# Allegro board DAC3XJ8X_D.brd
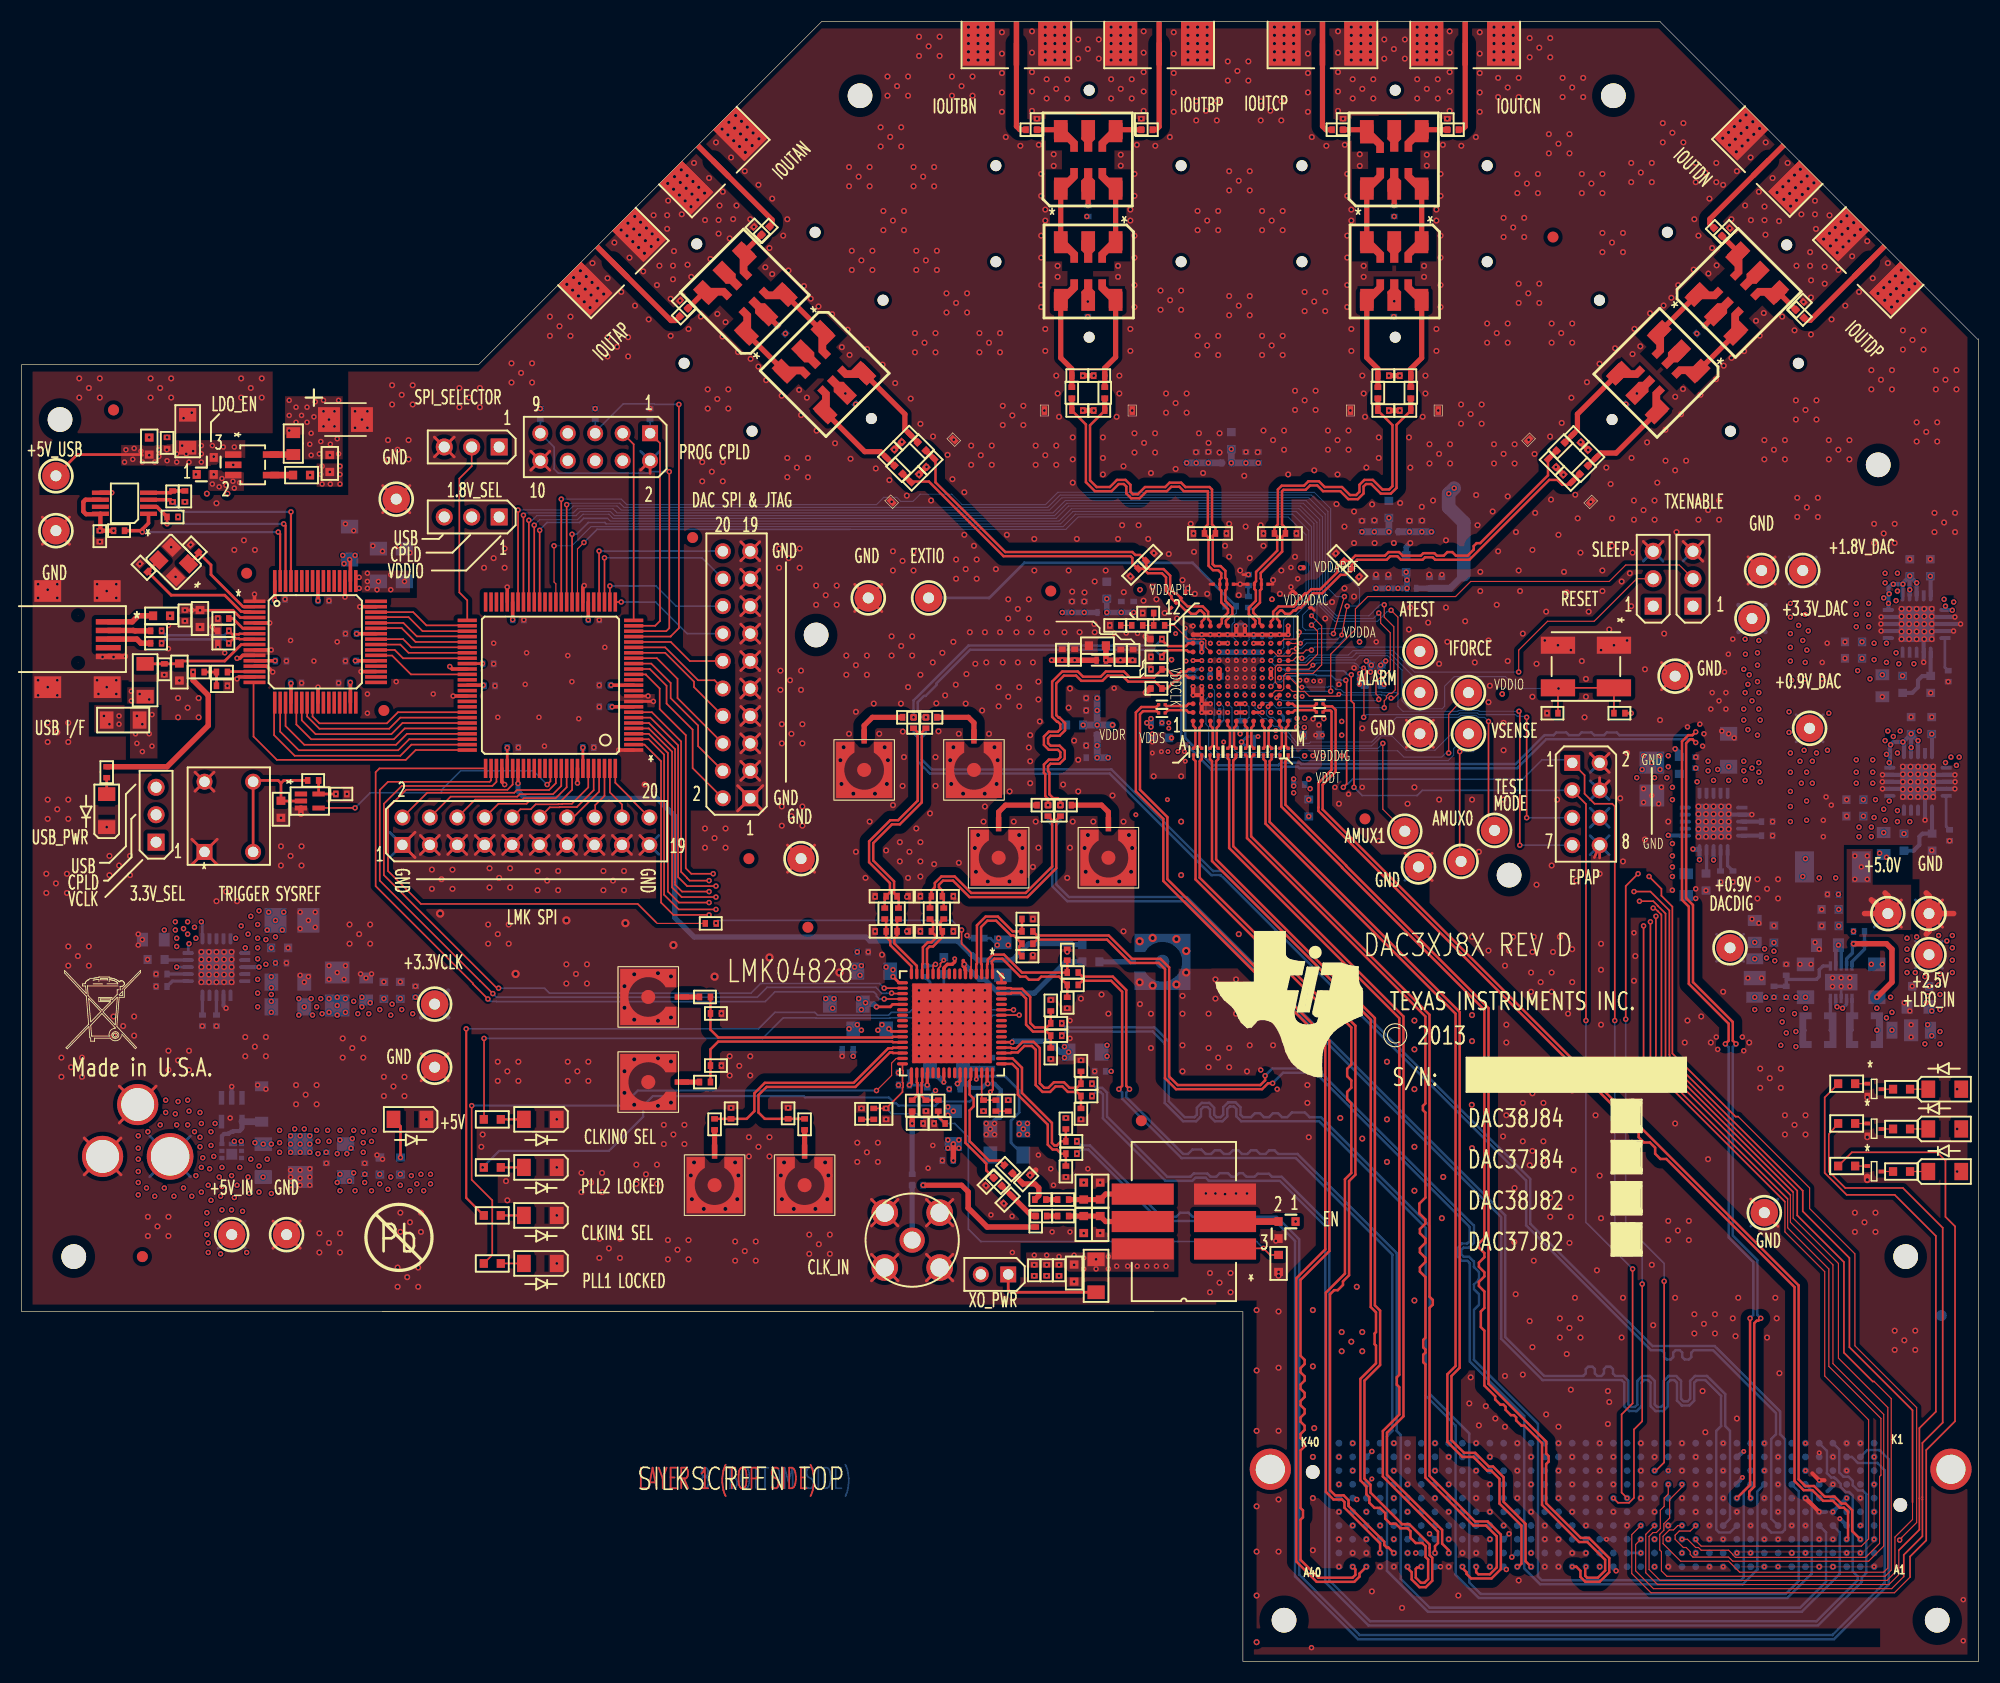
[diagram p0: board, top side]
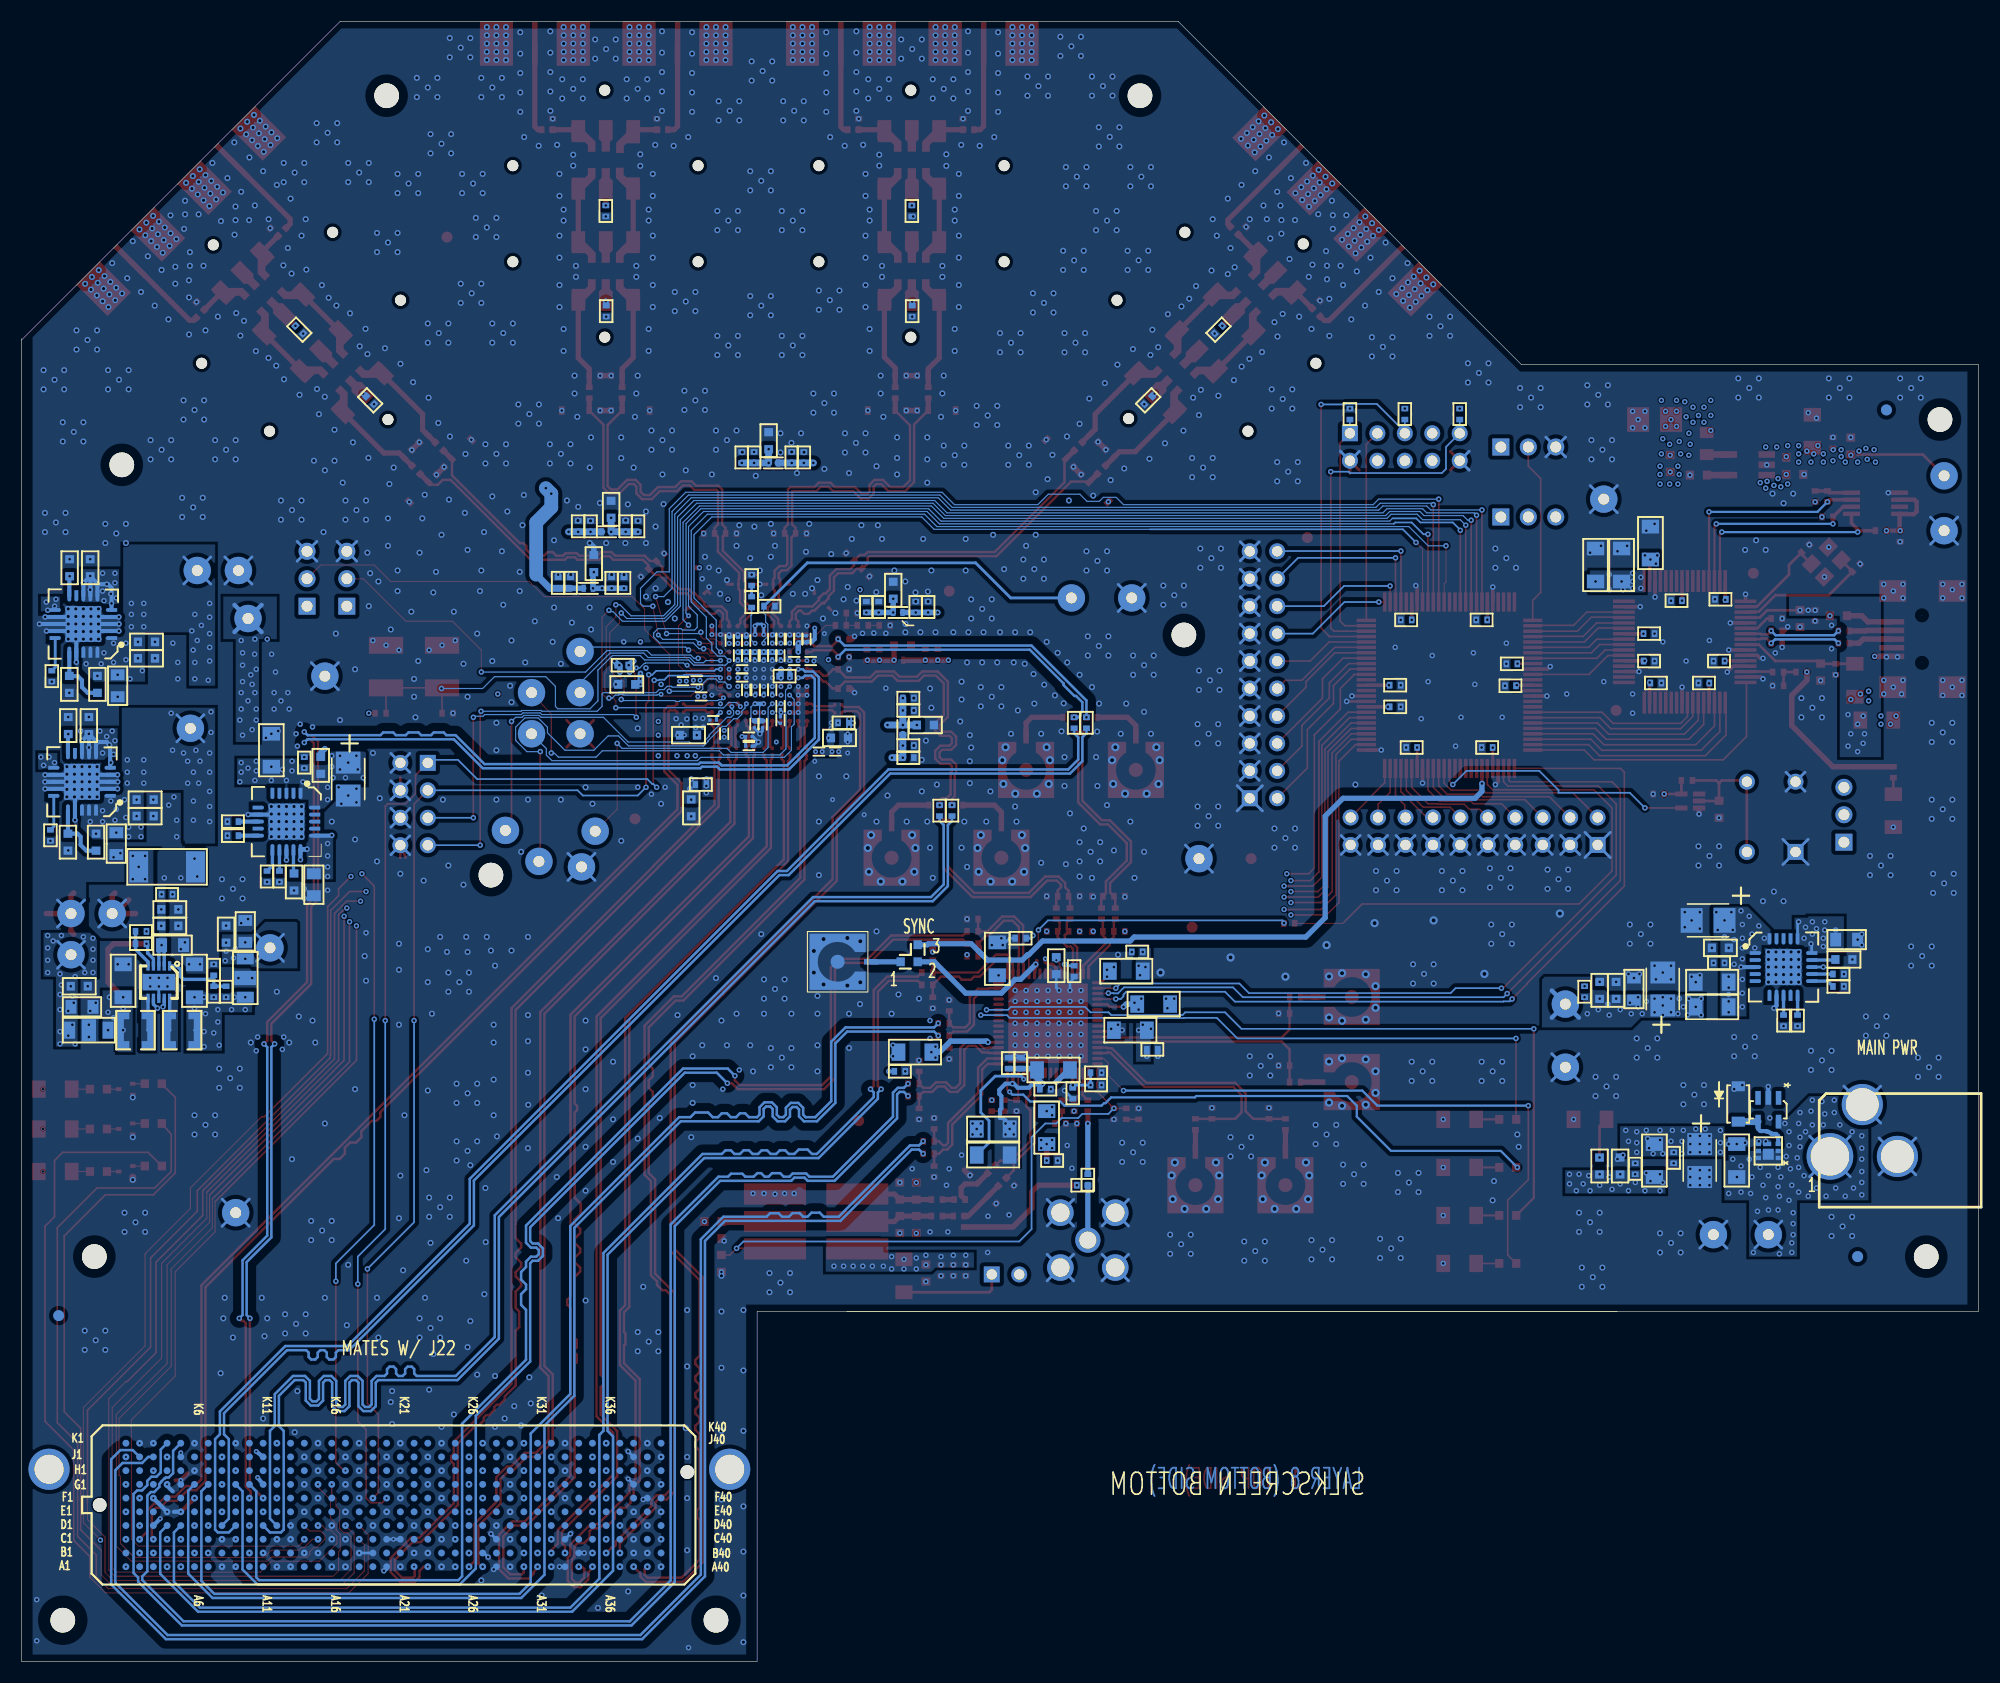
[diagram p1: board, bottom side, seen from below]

Outline 181.1 x 151.76 mm; copper layers: TOP, L2_GND, L3_PWR, L4_GND, L5_GND, L6_PWR, L7_GND, BOTTOM. Coordinates in mm from the lower left corner of the outline.
Outline path: 33.4,32.39 113.03,32.39 113.03,0 181.1,0 181.1,122.43 ; 104.77,32.39 0,32.39 0,120.02 42.29,120.02 74.04,151.76 151.64,151.76 181.1,122.3

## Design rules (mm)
constraint set DEFAULT: min track width 0.102
net group AOUT: nets ANOUT APOUT
net group B_OUT: nets BN_OUT BP_OUT
net group BOUT: nets BNOUT BPOUT
net group C_OUT: nets CN_OUT CP_OUT
net group CAR_SYSREF: nets CAR_SYSREFM CAR_SYSREFP
net group CLK: nets CLKN CLKP
net group CLK_LAO: nets CLK_LAO_0M CLK_LAO_0P
net group CLKIN1: nets CLKIN1N CLKIN1P
net group CLKLA: nets CLKLA_0N CLKLA_0P
net group COUT: nets CNOUT CPOUT
net group D_OUT: nets DN_OUT DP_OUT
net group DCLK_: nets DCLK_N DCLK_P
net group DCLKOUT0: nets DCLKOUT0N DCLKOUT0P
net group DCLKOUT2: nets DCLKOUT2N DCLKOUT2P
net group DCLKOUT8: nets DCLKOUT8N DCLKOUT8P
net group DIFFPAIR0: nets DP0_C2M_N_A DP0_C2M_P_A
net group DIFFPAIR1: nets DP7_C2M_N_A DP7_C2M_P_A
net group DIFFPAIR2: nets DP1_C2M_N_A DP1_C2M_P_A
net group DIFFPAIR3: nets DP2_C2M_N_A DP2_C2M_P_A
net group DIFFPAIR4: nets DP3_C2M_N_A DP3_C2M_P_A
net group DIFFPAIR5: nets DP4_C2M_N_A DP4_C2M_P_A
net group DIFFPAIR6: nets DP5_C2M_N_A DP5_C2M_P_A
net group DIFFPAIR7: nets DP6_C2M_N_A DP6_C2M_P_A
net group DIFFPAIR8: nets AN_OUT AP_OUT
net group DIFFPAIR9: nets GTXCLKM GTXCLKP
net group DIFFPAIR10: nets FMC_SYSREF_N FMC_SYSREF_P
net group DIFFPAIR11: nets FMC_DACCLK_N FMC_DACCLK_P
net group DOUT: nets DNOUT DPOUT
net group FPGA_CLK1: nets FPGA_CLK1N FPGA_CLK1P
net group FPGA_CLK2: nets FPGA_CLK2N FPGA_CLK2P
net group GTX_CLK: nets GTX_CLKM GTX_CLKP
net group IOUTA: nets IOUTAN IOUTAP
net group IOUTB: nets IOUTBN IOUTBP
net group IOUTC: nets IOUTCN IOUTCP
net group IOUTD: nets IOUTDN IOUTDP
net group OSCIN: nets OSCIN_N OSCIN_P
net group OUT_A: nets OUT_AN OUT_AP
net group OUT_B: nets OUT_BN OUT_BP
net group OUT_C: nets OUT_CN OUT_CP
net group OUT_D: nets OUT_DN OUT_DP
net group RX0: nets RX0N RX0P
net group RX1: nets RX1N RX1P
net group RX2: nets RX2N RX2P
net group RX3: nets RX3N RX3P
net group RX4: nets RX4N RX4P
net group RX5: nets RX5N RX5P
net group RX6: nets RX6N RX6P
net group RX7: nets RX7N RX7P
net group SDCLKOUT1: nets SDCLKOUT1N SDCLKOUT1P
net group SDCLKOUT3: nets SDCLKOUT3N SDCLKOUT3P
net group SDCLKOUT9: nets SDCLKOUT9N SDCLKOUT9P
net group SYNC: nets SYNCN SYNCP
net group SYS_: nets SYS_N SYS_P
net group SYSRE: nets SYSREF_M SYSREF_P
net group SYSREF: nets SYSREFN SYSREFP
net group USB_M: nets USB_DM USB_DP

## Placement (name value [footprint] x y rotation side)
C1  0.01uF  [0402]  94.49 79.25 0 top
C3  10uF  [0603]  119.13 78.99 270 bottom
C4  .1uF  [0201]  112.52 86.74 270 bottom
C5  .1uF  [0201]  113.28 86.74 270 bottom
C6  10uF  [0603]  99.57 94.01 180 top
C7  .1uF  [0201]  109.6 92.58 0 bottom
C8  0.01uF  [0402]  96.65 79.25 180 top
C9  .1uF  [0201]  108.08 92.58 180 bottom
C10  10uF  [0603]  128.14 101.6 90 bottom
C11  10uF  [0603]  119.38 85.72 0 bottom
C12  0.01uF  [0402]  82.04 87.38 0 top
C13  .1uF  [0201]  117.09 87.12 180 bottom
C14  .1uF  [0201]  111.63 89.92 90 bottom
C15  10uF  [0603]  125.09 90.42 0 bottom
C16  0.01uF  [0402]  84.2 87.38 180 top
C17  10uF  [0603]  100.43 99.14 90 bottom
C18  10uF  [0603]  105.41 85.47 180 bottom
C20  10uF  [0603]  111.96 112.98 90 bottom
C21  10uF  [0603]  97.46 86.66 180 bottom
C22  10uF  [0603]  126.54 106.63 90 bottom
C23  .1uF  [0201]  119.89 90.73 0 bottom
C24  .1uF  [0201]  118.62 90.81 0 bottom
C25  .1uF  [0201]  109.22 94.62 90 bottom
C26  .1uF  [0201]  108.46 94.62 90 bottom
C27  .1uF  [0201]  105.79 84.2 180 bottom
C28  .1uF  [0201]  107.31 84.2 0 bottom
C31  .1uF  [0201]  109.98 94.62 90 bottom
C32  .1uF  [0201]  115.57 94.49 90 bottom
C33  .1uF  [0201]  113.79 85.6 180 bottom
C34  .1uF  [0201]  113.79 84.71 180 bottom
C35  .1uF  [0201]  112.39 84.2 90 top
C36  .1uF  [0201]  111.63 84.2 90 top
C37  .1uF  [0201]  109.22 84.2 90 top
C38  .1uF  [0201]  108.46 84.2 90 top
C39  .1uF  [0201]  105.54 88.54 0 top
C40  .1uF  [0201]  105.54 87.78 0 top
C41  .01uF  [0603]  11.81 112.48 90 top
C42  27pF  [0402]  16 103 135 top
C43  100uF  [1206]  35.43 101.47 90 bottom
C44  4.7uF  [0603]  16.51 96.52 270 top
C45  .1uF  [0402]  15.11 96.8 270 top
C46  4.7uF  [0603]  14.61 91.57 270 top
C47  .01uF  [0603]  25.91 109.79 0 top
C48  .1uF  [0402]  13.21 91.82 270 top
C49  100uF  [1206]  30.35 103.51 90 bottom
C50  .1uF  [0402]  101.22 95.89 180 top
C51  22pF  [0402]  18.67 95.38 180 top
C52  22pF  [0402]  18.67 94.23 180 top
C53  .001uF  [0402]  104.27 97.03 180 top
C54  10uF  [1206]  15.37 113.85 90 top
C55  27pF  [0402]  11.3 101.22 135 top
C56  10uF  [1206]  33.02 101.47 90 bottom
C57  1uF  [0402]  83.82 52.58 270 bottom
C58  .1uF  [0402]  81.66 54.48 180 bottom
C59  0.01uF  [0402]  81.66 53.34 180 bottom
C60  .1uF  [0402]  80.01 50.67 270 top
C61  .68uF  [0402]  78.87 50.67 270 top
C62  3900pF  [0402]  90.17 51.44 270 top
C63  47pF  [0402]  89.03 51.44 270 top
C64  .1uF  [0402]  86.36 52.96 180 bottom
C65  0.01uF  [0402]  88.65 55.37 90 bottom
C66  1uF  [0402]  89.79 55.37 90 bottom
C67  .1uF  [0402]  97.28 62.61 0 top
C68  .1uF  [0402]  97.28 63.75 0 top
C69  0.01uF  [0402]  88.65 66.93 180 bottom
C70  0.01uF  [0402]  77.85 65.66 0 bottom
C71  0.01uF  [0402]  99.82 54.61 180 bottom
C72  0.01uF  [0402]  76.45 56.64 180 bottom
C73  0.01uF  [0402]  85.72 46.36 180 bottom
C74  .1uF  [0402]  98.55 53.47 0 top
C75  .1uF  [0402]  98.55 52.32 0 top
C78  .1uF  [0402]  83.69 51.44 90 top
C79  .1uF  [0402]  63.25 61.49 180 top
C80  .1uF  [0402]  94.28 42.74 180 top
C81  100pF  [0603]  97.41 35.94 90 top
C82  .1uF  [0402]  91.31 45.56 135 top
C83  .1uF  [0402]  63.25 53.62 180 top
C84  2200pF  [0402]  96.01 36.2 90 top
C85  10pF  [0402]  94.87 36.2 90 top
C86  .1uF  [0402]  95.76 57.91 180 top
C87  10uF  [0603]  85.34 64.39 270 bottom
C88  .1uF  [0402]  83.69 63.88 270 bottom
C89  .1uF  [0402]  95.76 59.06 180 top
C90  .1uF  [0402]  93.73 36.2 90 top
C91  .1uF  [0402]  64.13 49.71 270 top
C92  .1uF  [0402]  90.32 44.39 135 top
C93  .1uF  [0402]  72.47 49.71 270 top
C94  .1uF  [0402]  97.15 46.99 0 top
C95  .1uF  [0402]  97.15 48.13 0 top
C96  10uF  [0805]  12.19 66.8 180 bottom
C97  .1uF  [0402]  24 64.64 0 bottom
C98  1.0uF  [0603]  23.88 66.04 0 bottom
C99  47uF  [1206]  24.64 62.87 0 bottom
C100  4.7uF  [TANT_B]  25.02 68.58 0 bottom
C101  33uF  [TANT_B]  29.21 62.23 90 bottom
C102  10uF  [0805]  31.88 62.23 90 bottom
C103  .1uF  [0402]  36.45 61.98 90 bottom
C104  .01uF  [0603]  33.53 62.1 90 bottom
C105  .01uF  [0603]  35.05 62.1 90 bottom
C106  1.0uF  [0603]  12.45 64.96 180 bottom
C107  10uF  [0805]  154.05 71.88 270 bottom
C108  .1uF  [0402]  154.94 83.19 90 bottom
C109  1.0uF  [0603]  153.42 82.93 90 bottom
C110  47uF  [1206]  157.99 84.33 90 bottom
C113  4.7uF  [TANT_B]  150.88 81.66 270 bottom
C116  1.0uF  [0603]  155.89 72.14 270 bottom
C117  .01uF  [0603]  167.39 69.6 180 bottom
C119  .01uF  [0603]  175.77 62.48 180 bottom
C120  100pF  [0603]  116.33 36.83 90 top
C121  .1uF  [0402]  89.61 44.39 45 top
C122  .1uF  [0402]  82.42 51.44 90 top
C123  .01uF  [0603]  33.16 45.85 90 bottom
C124  .1uF  [0402]  28.21 46.61 270 bottom
C125  1uF  [0402]  31.76 45.59 90 bottom
C126  2.2uF  [0603]  174.75 101.22 90 bottom
C127  1.0uF  [0603]  176.66 101.22 90 bottom
C128  1.0uF  [0603]  169.54 94.36 180 bottom
C129  .01uF  [0603]  169.54 92.84 180 bottom
C130  10uF  [0805]  172.21 90.3 270 bottom
C133  .015uF  [0402]  178.31 91.19 270 bottom
C134  1.0uF  [0603]  176.78 86.61 90 bottom
C135  2.2uF  [0603]  174.88 86.61 90 bottom
C136  .015uF  [0402]  178.44 76.45 270 bottom
C137  1.0uF  [0603]  169.67 79.76 180 bottom
C138  .01uF  [0603]  169.67 78.23 180 bottom
C139  10uF  [0805]  172.34 75.69 270 bottom
C143  10uF  [0805]  167.13 66.29 180 bottom
C144  10uF  [0805]  175.51 60.58 180 bottom
C145  22uF  [1206]  165.1 62.99 90 bottom
C146  10uF  [0805]  160.4 67.56 90 bottom
C147  22uF  [1206]  171.7 62.99 90 bottom
C148  33pF  [0402]  162.18 61.98 90 bottom
C149  .01uF  [0603]  162.18 67.31 90 bottom
C150  1.0uF  [0603]  167.39 68.07 180 bottom
C151  4.7uF  [TANT_B]  29.97 114.94 0 top
C152  .1uF  [0402]  52.45 84.58 180 bottom
C153  .1uF  [0402]  45.47 84.58 180 bottom
C154  .1uF  [0402]  43.18 92.33 180 bottom
C155  .1uF  [0402]  43.31 90.3 180 bottom
C156  .1uF  [0402]  53.98 88.35 0 bottom
C157  .1uF  [0402]  29.84 90.55 0 bottom
C158  .1uF  [0402]  27.94 98.17 180 bottom
C159  .1uF  [0402]  30.48 95.12 0 bottom
C160  .1uF  [0402]  25.4 90.55 180 bottom
C161  .1uF  [0402]  24 92.58 180 bottom
C162  .1uF  [0402]  53.98 90.35 0 bottom
C163  .1uF  [0402]  23.88 98.3 180 bottom
C164  .1uF  [0402]  30.48 92.58 0 bottom
C165  .1uF  [0402]  52.96 96.39 180 bottom
C166  .1uF  [0402]  45.97 96.39 180 bottom
C167  .1uF  [0402]  111.89 97.66 180 bottom
C168  .001uF  [0402]  141.68 87.76 180 top
C169  .1uF  [0201]  111.63 94.62 90 bottom
C170  .1uF  [0201]  114.81 94.49 90 bottom
C171  .1uF  [0201]  114.43 91.06 180 bottom
C172  .01uF  [0201]  110.87 94.62 90 bottom
C173  .01uF  [0201]  114.05 94.49 90 bottom
C174  .1uF  [0201]  114.43 91.82 180 bottom
C175  .1uF  [0201]  110.87 87.12 90 bottom
C176  .1uF  [0201]  116.08 85.85 270 bottom
C177  .1uF  [0201]  112.39 89.92 90 bottom
C178  .1uF  [0201]  113.16 89.92 90 bottom
C179  .1uF  [0201]  114.05 89.92 90 bottom
C180  .1uF  [0201]  110.87 88.39 270 bottom
C181  .1uF  [0201]  118.21 89.31 0 bottom
C182  .1uF  [0201]  110.87 93.09 270 bottom
C183  .1uF  [0201]  111.63 93.09 270 bottom
C184  .1uF  [0201]  112.39 93.09 270 bottom
C185  .1uF  [0201]  113.28 93.09 270 bottom
C186  .1uF  [0201]  114.05 93.09 270 bottom
C187  .1uF  [0201]  114.81 93.09 270 bottom
C188  .1uF  [0201]  109.98 84.2 90 top
C189  .1uF  [0201]  110.74 84.2 90 top
C190  .1uF  [0201]  120.14 87.86 180 top
C191  .1uF  [0201]  120.14 88.62 180 top
C192  .1uF  [0201]  116.46 84.2 90 top
C193  .1uF  [0201]  117.22 84.2 90 top
C194  .1uF  [0201]  115.7 84.2 90 top
C195  .1uF  [0201]  114.93 84.2 90 top
C196  .1uF  [0201]  113.28 84.2 90 top
C197  .1uF  [0201]  114.05 84.2 90 top
C198  .1uF  [0402]  84.84 51.44 90 top
C199  .01uF  [0603]  24 78.87 270 top
C200  .1uF  [0402]  29.59 80.28 0 top
C206  .1uF  [0402]  94.36 41.22 180 top
C207  .1uF  [0402]  167.64 70.99 0 bottom
C235  47uF  [TANT_B]  25.79 46.36 270 bottom
C236  .1uF  [0402]  7.24 104.14 90 top
C340  1uF  [0402]  81.15 69.22 90 top
C341  1uF  [0402]  79.88 69.22 90 top
C343  0.01uF  [0402]  126.49 99.82 90 bottom
C344  1uF  [0402]  125.35 99.82 90 bottom
C345  0.01uF  [0402]  131.44 99.82 90 bottom
C346  1uF  [0402]  130.3 99.82 90 bottom
C347  0.01uF  [0402]  96.32 93.17 90 top
C348  1uF  [0402]  97.46 93.17 90 top
C349  0.01uF  [0402]  102.87 93.14 90 top
C350  1uF  [0402]  101.73 93.14 90 top
C351  0.01uF  [0402]  102.92 97.59 90 bottom
C352  1uF  [0402]  101.78 97.59 90 bottom
C353  0.01uF  [0402]  98.35 97.59 90 bottom
C354  1uF  [0402]  97.21 97.59 90 bottom
C355  0.01uF  [0402]  124.05 105.05 90 bottom
C356  1uF  [0402]  125.2 105.05 90 bottom
C357  0.01uF  [0402]  128.45 105.05 90 bottom
C358  1uF  [0402]  129.59 105.05 90 bottom
C359  0.01uF  [0402]  113.31 111.43 90 bottom
C360  1uF  [0402]  114.45 111.43 90 bottom
C361  0.01uF  [0402]  109.83 111.43 90 bottom
C362  1uF  [0402]  108.71 111.43 90 bottom
C363  0.01uF  [0402]  99.03 89.15 180 bottom
C364  1uF  [0402]  99.03 88.01 180 bottom
C365  0.01uF  [0402]  99.03 84.76 180 bottom
C366  1uF  [0402]  99.03 83.64 180 bottom
D1  LED BLUE  [LED_1206]  35.94 50.17 0 top
D2  LED BLUE  [LED_1206]  177.99 52.96 180 top
D3  LED BLUE  [LED_1206]  177.99 49.28 180 top
D4  LED GREEN  [LED_1206]  48.01 50.17 0 top
D5  LED GREEN  [LED_1206]  48.01 41.28 0 top
D6  LED GREEN  [LED_1206]  48.01 36.83 0 top
D7  LED GREEN  [LED_1206]  48.01 45.72 0 top
D8  LED AMBER  [LED_1206]  7.87 78.74 270 top
D9  MMSZ5235B  [DIODE_SM_SOD_123]  22.23 51.59 270 bottom
D11  LED BLUE  [LED_1206]  177.99 45.34 180 top
F1  FUSE 2.0A 63V FAST  [1206]  22.36 46.36 90 bottom
FB2  120 OHM @ 100MHz  [1206]  86.23 49.4 90 bottom
FB3  120 OHM @ 100MHz  [1206]  91.19 49.28 180 bottom
FB4  120 OHM @ 100MHz  [1206]  91.19 46.86 0 bottom
FB5  120 OHM @ 100MHz  [1206]  85.6 54.74 180 bottom
FB6  120 OHM @ 100MHz  [1206]  78.87 63.88 0 bottom
FB7  120 OHM @ 100MHz  [1206]  78.49 58.42 0 bottom
FB8  120 OHM @ 100MHz  [1206]  76.33 60.83 0 bottom
FB9  120 OHM @ 100MHz  [1206]  98.42 56.39 180 bottom
FB10  120 OHM @ 100MHz  [1206]  90.8 65.02 270 bottom
FB15  50 OHM @ 100MHz  [1206]  11.43 90.81 90 top
FB16  50 OHM @ 100MHz  [1206]  9.4 87.12 0 top
FB17  120 OHM @ 100MHz  [1206]  99.44 35.69 270 top
FB18  120 OHM @ 100MHz  [IND_0402]  99.92 92.66 0 top
FB19  120 OHM @ 100MHz  [IND_0402]  128.65 99.31 180 bottom
FB20  50 OHM @ 100MHz  [1206]  29.98 46.36 90 bottom
FB24  50 OHM @ 100MHz  [1206]  24.64 60.58 180 bottom
FB25  120 OHM @ 100MHz  [IND_0402]  100 97.08 0 bottom
FB29  120 OHM @ 100MHz  [IND_0402]  99.54 86.23 90 bottom
FB30  27uF  [1206_BEAD_NFM31P]  160.4 63.25 90 bottom
FB31  27uF  [1206_BEAD_NFM31P]  174.88 58.42 0 bottom
FB32  120 OHM @ 100MHz  [IND_0402]  111.53 110.92 0 bottom
FB33  120 OHM @ 100MHz  [IND_0402]  126.97 104.55 180 bottom
FB34  1K  [1810]  167.64 73.53 180 bottom
FB36  1K @ 100MHz  [0603]  28.52 110.87 90 top
GP1  GND PAD  [TESTPAD20_30]  80.52 107.33 315 top
GP2  GND PAD  [TESTPAD20_30]  86.27 113.08 135 top
GP3  GND PAD  [TESTPAD20_30]  94.66 115.77 270 top
GP4  GND PAD  [TESTPAD20_30]  102.78 115.77 90 top
GP5  GND PAD  [TESTPAD20_30]  122.98 115.77 270 top
GP6  GND PAD  [TESTPAD20_30]  131.11 115.77 90 top
GP7  GND PAD  [TESTPAD20_30]  145.22 107.32 45 top
GP8  GND PAD  [TESTPAD20_30]  139.47 113.06 225 top
J1  SMP_PCB_SMT  [SMP_B120]  77.98 82.51 180 top
J2  SMA END LAUNCH  [SMA_SMEL_DUAL_PSF-S01_250X215]  53.24 130.95 45 top
J3  SMP_PCB_SMT  [SMP_B120]  88.14 82.51 180 top
J4  SMA END LAUNCH  [SMA_SMEL_DUAL_PSF-S01_250X215]  62.58 140.29 45 top
J5  SMP_PCB_SMT  [SMP_B120]  90.42 74.38 180 top
J6  SMA END LAUNCH  [SMA_SMEL_DUAL_PSF-S01_250X215]  105.28 151.76 0 top
J7  SMP_PCB_SMT  [SMP_B120]  100.58 74.38 180 top
J8  SMA END LAUNCH  [SMA_SMEL_DUAL_PSF-S01_250X215]  92.07 151.76 0 top
J9  SMA END LAUNCH  [SMA_SMEL_DUAL_PSF-S01_250X215]  120.4 151.76 0 top
J10  SMA END LAUNCH  [SMA_SMEL_DUAL_PSF-S01_250X215]  133.6 151.76 0 top
J11  SMA END LAUNCH  [SMA_SMEL_DUAL_PSF-S01_250X215]  163.1 140.34 315 top
J12  SMA END LAUNCH  [SMA_SMEL_DUAL_PSF-S01_250X215]  172.44 131 315 top
J13  SMP_PCB_SMT  [SMP_B120]  58 61.49 90 top
J14  USB_MINI_AB  [CON_SMRT_USBMNE20_F]  4.57 94.62 0 top
J15  HTSW-105-07-G-D  [HDR_THVT_2X5_100_M]  58.17 113.67 270 top
J16  CON_SMVT_40x10_SEAM  [CON_SMVT_40X10_ASP-134487-01]  146.69 14.48 0 bottom
J17  SMB_THVT_REC  [SMA_THVT_312X312]  82.42 38.99 180 top
J18  SMP_PCB_SMT  [SMP_B120]  58 53.62 90 top
J19  SMP_PCB_SMT  [SMP_B120]  64.13 44.08 180 top
J20  SMP_PCB_SMT  [SMP_B120]  72.47 44.08 180 top
J21  HMTSW-104-07-G-D-.240  [HDR_THVT_2X4_100_M]  143.51 83.16 0 top
J22  SMP_PCB_SMT  [SMP_B120]  105.58 64.75 90 bottom
J23  CONN JACK PWR  [CON_RAPC722_JACK_THVT_3]  10.62 46.74 90 bottom
J24  HMTSW-110-07-G-D-.240  [HDR_THVT_2X10_100_M]  67.44 79.88 180 top
J25  HMTSW-110-07-G-D-.240  [HDR_THVT_2X10_100_M]  35.24 75.56 90 top
JP1  Jumper_1x3_100_430L  [HDR_THVT_1X3_100_M]  154.69 97.66 180 top
JP2  HDR, THVT, 2POS  [HDR_THVT_1X2_100_M]  91.31 35.81 270 top
JP3  Jumper_1x3_100_430L  [HDR_THVT_1X3_100_M]  44.2 112.4 270 top
JP4  Jumper_1x3_100_430L  [HDR_THVT_1X3_100_M]  151 97.66 180 top
JP5  Jumper_1x3_100_430L  [HDR_THVT_1X3_100_M]  44.2 105.92 270 top
JP6  Jumper_1x3_100_430L  [HDR_THVT_1X3_100_M]  12.45 75.82 180 top
L17  2.2uH  [LPS3015]  170.56 58.42 0 bottom
L18  2.2uH  [LPS3015]  166.24 58.42 180 bottom
MT1  STANDOFF,  HEX, 4-40 X 1 1/4", ALUM  [MFG125_PLATED]  171.83 110.74 0 top
MT2  STANDOFF,  HEX, 4-40 X 1 1/4", ALUM  [MFG125_PLATED]  4.83 37.47 270 top
MT3  STANDOFF,  HEX, 4-40 X 1 1/4", ALUM  [MFG125_PLATED]  147.32 144.91 0 top
MT4  STANDOFF,  HEX, 4-40 X 1 1/4", ALUM  [MFG125_PLATED]  174.37 37.47 0 top
MT5  STANDOFF,  HEX, 4-40 X 1 1/4", ALUM  [MFG125_PLATED]  77.6 144.91 0 top
MT6  STANDOFF,  HEX, 4-40 X 1 1/4", ALUM  [MFG125_PLATED]  137.67 72.77 90 top
MT7  STANDOFF,  HEX, 4-40 X 1 1/4", ALUM  [MFG125_PLATED]  73.53 95 0 top
MT8  STANDOFF,  HEX, 4-40 X 1 1/4", ALUM  [MFG125_PLATED]  3.56 114.94 90 top
NOREF  -  []  181.1 122.3 0 top
NOREF#2  -  [unnamed#2]  107.31 138.43 0 top
NOREF#3  -  [unnamed#2]  178.56 17.78 0 top
NOREF#4  -  [unnamed#2]  177.29 3.81 0 top
NOREF#5  -  [unnamed#2]  116.84 3.81 0 top
NOREF#6  -  []  135 142.54 0 top
NOREF#7  -  [unnamed#2]  146.03 125.98 315 top
NOREF#8  -  []  126.75 53.34 0 top
NOREF#9  -  []  116.84 3.81 90 top
NOREF#10  -  [unnamed#3]  11.18 37.47 270 top
NOREF#11  -  []  113.03 0 0 top
NOREF#12  -  [unnamed#2]  79.73 125.98 45 top
NOREF#13  -  []  140.08 38.1 0 top
NOREF#14  -  [unnamed#2]  67.6 113.86 45 top
NOREF#15  -  []  116.84 3.81 0 top
NOREF#16  -  [unnamed#3]  95.25 99.06 270 top
NOREF#17  -  [unnamed#3]  141.73 131.83 90 top
NOREF#18  -  []  113.03 0 90 top
NOREF#19  -  [unnamed#3]  72.77 67.95 270 top
NOREF#20  -  [unnamed#2]  147.2 114.93 315 top
NOREF#21  -  [unnamed#2]  107.31 129.54 0 top
NOREF#22  -  []  -84.07 333.38 0 top
NOREF#23  -  []  42.29 120.02 0 top
NOREF#24  -  [unnamed#2]  98.81 145.42 0 top
NOREF#25  -  [unnamed#2]  152.32 132.27 315 top
NOREF#26  -  [unnamed#2]  61.32 120.15 45 top
NOREF#27  -  []  118.62 61.38 0 top
NOREF#28  -  [unnamed#3]  124.33 77.98 270 top
NOREF#29  -  [unnamed#3]  103.63 50.04 270 top
NOREF#30  -  [unnamed#2]  135.64 129.54 0 top
NOREF#31  -  [unnamed#3]  8.51 115.82 90 top
NOREF#32  -  [unnamed#3]  62.1 104.01 270 top
NOREF#33  -  [unnamed#2]  158.15 113.86 315 top
NOREF#34  -  []  59.44 120.02 0 top
NOREF#35  -  [unnamed#2]  62.48 131.19 45 top
NOREF#36  -  [unnamed#2]  78.65 115.03 45 top
NOREF#37  -  [unnamed#2]  118.5 138.43 0 top
NOREF#38  -  [unnamed#2]  90.17 129.54 0 top
NOREF#39  -  [unnamed#2]  127.13 122.56 0 top
NOREF#40  -  []  140.08 41.91 0 top
NOREF#41  -  [unnamed#2]  115.57 17.78 0 top
NOREF#42  -  []  3.35 52.17 0 top
NOREF#43  -  []  74.04 151.76 0 top
NOREF#44  -  []  19.77 61.25 0 top
NOREF#45  -  []  251.84 71.75 0 top
NOREF#46  -  []  116.84 3.81 90 top
NOREF#47  -  [unnamed#2]  98.81 122.56 0 top
NOREF#48  -  []  116.84 3.81 0 top
NOREF#49  -  []  140.08 45.72 0 top
NOREF#50  -  [unnamed#2]  127.13 145.42 0 top
NOREF#51  -  [unnamed#3]  67.31 74.3 270 top
NOREF#52  -  []  383.92 171.7 0 top
NOREF#53  -  [unnamed#2]  163.36 131.1 315 top
NOREF#54  -  [unnamed#2]  135.64 138.43 0 top
NOREF#55  -  []  32.89 37.97 0 top
NOREF#56  -  [unnamed#2]  90.17 138.43 0 top
NOREF#57  -  []  116.84 3.81 90 top
NOREF#58  -  [unnamed#2]  164.44 120.14 315 top
NOREF#59  -  []  113.03 0 90 top
NOREF#60  -  []  -89.89 338.61 0 top
NOREF#61  -  []  -100.58 -135.89 0 top
NOREF#62  -  []  0 32.39 0 top
NOREF#63  -  []  140.08 49.53 0 top
NOREF#64  -  [unnamed#2]  118.5 129.54 0 top
NOREF#65  -  [unnamed#2]  73.44 132.27 45 top
NOREF#66  -  []  7.43 60.48 0 top
NOREF#67  -  [unnamed#3]  177.67 32 270 bottom
NOREF#68  -  [unnamed#3]  11.18 37.47 90 bottom
NOREF#69  -  [unnamed#3]  8.51 115.82 270 bottom
PP1  PROBE POINT  [PROBE_POINT_22PAD]  119.13 81.66 0 top
PP2  PROBE POINT  [PROBE_POINT_22PAD]  106.43 92.71 0 top
PP3  PROBE POINT  [PROBE_POINT_22PAD]  123.82 94.36 0 top
PP4  PROBE POINT  [PROBE_POINT_22PAD]  137.03 89.53 0 top
PP5  PROBE POINT  [PROBE_POINT_22PAD]  103.5 99.19 0 top
PP6  PROBE POINT  [PROBE_POINT_22PAD]  115.72 98.3 0 top
PP7  PROBE POINT  [PROBE_POINT_22PAD]  106.43 85.47 0 top
PP9  PROBE POINT  [PROBE_POINT_22PAD]  118.74 83.82 0 top
PP10  PROBE POINT  [PROBE_POINT_22PAD]  118.62 101.22 0 top
PP11  PROBE POINT  [PROBE_POINT_22PAD]  100.96 86.66 0 top
Q1  CSD17313Q2  [MOSFET_8_2MMX2MM_0P65]  19.44 47.24 90 bottom
Q2  DTC114EET1G  [SOT_416_3_63X31]  170.81 49.94 0 top
Q3  DTC114EET1G  [SOT_416_3_63X31]  170.81 53.62 0 top
Q4  DTC114EET1G  [SOT_416_3_63X31]  170.81 46 0 top
R1  0  [0805]  25.15 112.71 90 top
R2  0  [0402]  61.3 124.87 45 top
R3  49.9  [0402]  82.68 109.48 225 top
R4  0  [0402]  95 78.74 270 top
R5  0  [0402]  81.15 110.29 135 top
R6  49.9  [0402]  105.03 90.04 0 top
R7  0  [0402]  96.14 78.74 270 top
R8  49.9  [0402]  84.12 110.92 225 top
R9  0  [0402]  83.31 112.45 135 top
R10  49.9  [0402]  105.03 91.82 0 top
R11  0  [0402]  70.33 123.25 315 bottom
R12  0  [0402]  68.13 132.41 315 top
R13  49.9  [0402]  105.03 92.96 0 top
R14  0  [0402]  68.85 132.41 45 top
R15  0  [0402]  61.3 125.58 315 top
R16  0  [0402]  82.55 86.87 270 top
R17  0  [0402]  104.14 141.76 0 top
R18  0  [0402]  83.69 86.87 270 top
R19  0  [0402]  103.63 142.27 270 top
R20  49.9  [0402]  99.74 115.77 0 top
R21  0  [0402]  100.24 117.42 90 top
R22  0  [0402]  93.98 142.27 90 top
R23  49.9  [0402]  97.7 115.77 0 top
R24  0  [0402]  98.71 134.24 270 bottom
R25  0  [0402]  97.2 117.42 90 top
R26  49.9  [0402]  123.43 100.75 315 top
R27  0  [0402]  93.47 141.76 180 top
R28  49.9  [0402]  121.99 102.19 135 top
R29  49.9  [0402]  115.44 104.39 180 top
R30  0  [0402]  121.79 141.76 180 top
R31  49.9  [0402]  117.47 104.39 0 top
R32  49.9  [0402]  126.03 115.77 180 top
R33  0  [0402]  125.52 117.42 90 top
R34  49.9  [0402]  111 104.39 0 top
R35  49.9  [0402]  108.97 104.39 180 top
R36  49.9  [0402]  102.99 100.78 225 top
R37  49.9  [0402]  128.06 115.77 180 top
R38  0  [0402]  128.57 117.42 90 top
R39  49.9  [0402]  104.42 102.21 45 top
R40  0  [0402]  127.04 134.24 270 bottom
R41  0  [0402]  131.95 142.27 270 top
R42  0  [0402]  132.46 141.76 0 top
R43  0  [0402]  164.55 124.74 315 top
R44  0  [0402]  164.55 125.46 45 top
R45  49.9  [0402]  143.07 109.47 315 top
R46  0  [0402]  144.59 110.28 45 top
R47  0  [0402]  142.44 112.43 45 top
R48  49.9  [0402]  141.63 110.91 315 top
R49  0  [0402]  155.4 123.25 225 bottom
R50  0  [0402]  157.01 132.28 135 top
R51  0  [0603]  12.95 96.77 180 top
R52  12K  [0402]  18.67 96.52 180 top
R53  4.7K  [0402]  16.38 91.57 0 top
R54  1K  [0402]  18.54 91.57 0 top
R55  10  [0402]  12.45 94.23 0 top
R56  10  [0402]  12.45 95.38 0 top
R57  1K  [0402]  58.17 115.44 90 bottom
R58  10K  [0402]  9.02 104.65 180 top
R59  2.2K  [0402]  13.97 107.82 90 top
R60  10K  [0402]  13.97 105.92 0 top
R61  10K  [0402]  18.54 90.3 180 top
R62  1K  [0402]  103.25 95.89 180 top
R63  1K  [0402]  147.88 87.76 180 top
R64  10K  [0402]  15.11 107.82 270 top
R65  620  [0402]  91.31 51.44 90 top
R66  39K  [0402]  77.72 50.67 90 top
R67  240  [0402]  96.77 60.96 270 top
R68  240  [0402]  96.77 65.41 90 top
R69  240  [0402]  93.09 65.28 0 top
R70  240  [0402]  93.09 68.71 0 top
R71  0  [0402]  76.83 116.71 315 bottom
R72  0  [0402]  148.84 116.71 45 bottom
R73  130  [0603]  98.3 43.53 270 top
R74  82  [0603]  99.82 43.53 90 top
R75  240  [0402]  64.26 59.97 0 top
R76  240  [0402]  64.26 55.14 0 top
R77  49.9  [0402]  92.97 44.63 45 top
R78  130  [0603]  98.3 40.43 90 top
R79  240  [0402]  95.25 56.26 270 top
R80  240  [0402]  95.25 60.71 90 top
R81  750  [0603]  43.56 50.17 180 top
R82  750  [0603]  43.56 41.28 180 top
R83  240  [0402]  65.66 50.72 90 top
R84  240  [0402]  70.94 50.72 90 top
R85  750  [0603]  43.56 36.83 180 top
R86  750  [0603]  43.56 45.72 180 top
R87  82  [0603]  99.82 40.43 270 top
R88  100  [0402]  96.39 41.22 180 top
R89  200  [0402]  85.72 67.56 0 top
R90  0  [0402]  12.95 63.61 0 bottom
R91  0  [0402]  12.95 62.47 0 bottom
R92  0  [0402]  16.73 59.31 90 bottom
R93  0  [0402]  18.03 59.31 90 bottom
R94  0  [0402]  157.24 72.64 90 bottom
R95  0  [0402]  158.38 72.64 90 bottom
R96  0  [0402]  161.54 76.42 180 bottom
R97  0  [0402]  161.54 77.72 180 bottom
R98  200  [0402]  83.69 67.56 180 top
R99  49.9  [0402]  91.26 42.74 225 top
R100  49.9  [0402]  82.93 49.78 0 top
R101  1K  [0402]  7.87 82.3 270 top
R102  0  [0402]  122.3 142.27 270 top
R103  0  [0402]  157.73 132.28 225 top
R104  49.9  [0402]  84.96 49.78 180 top
R105  100  [0402]  84.07 69.22 90 top
R106  100  [0402]  85.34 69.22 90 top
R107  10K  [0402]  26.98 81.53 180 top
R108  0  [0402]  93.09 67.56 0 top
R109  0  [0402]  93.09 66.42 0 top
R110  1K  [0402]  48.01 115.44 90 bottom
R111  10K  [0402]  53.09 115.44 90 bottom
R112  49.9  [0402]  105.03 94.62 0 top
R113  0  [0402]  63.78 68.3 0 top
R114  49.9  [0201]  106.63 97.74 225 top
R115  100  [0402]  83.69 70.82 0 top
R116  100  [0402]  85.72 70.82 180 top
R117  49.9  [0201]  107.52 98.63 225 top
R118  49.9  [0201]  111.85 99.69 0 top
R119  0  [0603]  168.91 53.47 0 top
R120  0  [0603]  168.91 45.85 0 top
R121  0  [0603]  168.91 49.78 0 top
R122  240  [0402]  98.04 55.12 90 top
R123  240  [0402]  98.04 50.67 270 top
R124  240  [0402]  96.65 45.34 270 top
R125  240  [0402]  96.65 49.78 90 top
R126  10K  [0603]  173.99 49.28 180 top
R127  10K  [0603]  173.99 52.96 180 top
R128  10K  [0603]  173.99 45.34 180 top
R129  49.9  [0201]  110.59 99.69 0 top
R130  49.9  [0201]  113.79 99.69 0 top
R131  49.9  [0201]  115.05 99.69 0 top
R132  49.9  [0201]  119.02 97.74 135 top
R133  0  [0402]  105.28 95.89 0 top
R134  49.9  [0201]  118.14 98.63 135 top
R135  1.91K  [0402]  113.54 98.04 90 bottom
R136  0  [0402]  113.54 100.08 270 bottom
R138  100  [0402]  96.39 42.74 180 top
R143  10K  [0603]  35.06 45.85 270 bottom
R148  475K  [0402]  170.05 66.42 180 bottom
R150  95.3K  [0402]  163.32 61.98 270 bottom
R151  150K  [0402]  170.05 67.56 0 bottom
R153  182K  [0402]  163.32 64.01 270 bottom
R173  2.87K  [0603]  176.69 90.42 90 bottom
R174  3.65K  [0603]  174.09 90.42 270 bottom
R175  4.99K  [0603]  176.81 75.82 270 bottom
R176  634  [0603]  174.21 75.82 270 bottom
R177  0  [0402]  82.42 44.58 90 bottom
R178  0  [0402]  13.46 112.78 90 top
R179  121  [0402]  81.53 67.56 0 top
R180  121  [0402]  79.5 67.56 180 top
R181  121  [0402]  79.5 70.82 180 top
R182  121  [0402]  81.53 70.82 0 top
R183  0  [0402]  127 124.97 270 bottom
R184  0  [0402]  98.68 124.97 90 bottom
R185  0  [0402]  82.93 44.07 0 bottom
R186  0  [0402]  93.85 40.71 90 top
R187  0  [0402]  82.55 86.87 90 bottom
R188  0  [0402]  83.69 86.87 90 bottom
R189  0  [0402]  96.14 78.74 90 bottom
R190  0  [0402]  95 78.74 90 bottom
R191  0  [0402]  110.49 91.19 0 bottom
R192  0  [0402]  118.24 81.15 0 bottom
R193  0  [0402]  125.48 92.2 180 bottom
R194  0  [0402]  105.03 86.87 0 bottom
R195  49.9  [0402]  80.39 111.79 225 top
R196  49.9  [0402]  81.84 113.23 225 top
R197  49.9  [0402]  99.73 119 0 top
R198  49.9  [0402]  97.7 119 0 top
R199  49.9  [0402]  126.03 119 180 top
R200  49.9  [0402]  128.06 119 180 top
R201  49.9  [0402]  145.35 111.76 315 top
R202  49.9  [0402]  143.93 113.2 315 top
SJP1  JUMPER_L_0603_SMT  [JUMPER_SMD_L_0603]  116.84 40.71 180 top
SJP2  JUMPER_L_0603_SMT  [JUMPER_SMD_L_0603]  98.68 64.75 180 bottom
SJP3  JUMPER_L_0603_SMT  [JUMPER_SMD_L_0603]  17.27 109.86 0 top
SW1  SW RESET  [SW_SMVT_RESET]  144.78 92.08 270 top
SW2  B3F-1002  [SW_THVT_SPST_4_B3F]  19.18 78.17 90 top
T1  JTX-2-10TA+  [TFMR_6_RF_DUAL_FOOTPRINT]  74.26 119.32 225 top
T2  MABA-007159-000000  [TFMR_6_RF_DUAL_FOOTPRINT]  66.99 126.6 45 top
T3  JTX-2-10TA+  [TFMR_6_RF_DUAL_FOOTPRINT]  98.71 128.68 180 top
T4  MABA-007159-000000  [TFMR_6_RF_DUAL_FOOTPRINT]  98.71 138.97 0 top
T5  JTX-2-10TA+  [TFMR_6_RF_DUAL_FOOTPRINT]  127.04 128.68 180 top
T6  MABA-007159-000000  [TFMR_6_RF_DUAL_FOOTPRINT]  127.04 138.97 0 top
T7  JTX-2-10TA+  [TFMR_6_RF_DUAL_FOOTPRINT]  151.47 119.32 135 top
T8  MABA-007159-000000  [TFMR_6_RF_DUAL_FOOTPRINT]  158.74 126.6 315 top
TP1  ORN  [TP_THVT_100_RND]  128.02 76.84 0 top
TP2  ORN  [TP_THVT_100_RND]  133.22 74.04 0 top
TP3  BLK  [TP_THVT_100_RND_GND]  78.36 98.43 0 top
TP4  BLK  [TP_THVT_100_RND_GND]  161.29 41.53 0 top
TP5  BLK  [TP_THVT_100_RND_GND]  38.23 54.99 0 top
TP6  BLK  [TP_THVT_100_RND_GND]  34.67 107.57 0 top
TP7  BLK  [TP_THVT_100_RND_GND]  72.14 74.3 0 top
TP8  BLK  [TP_THVT_100_RND_GND]  153.03 91.19 0 top
TP9  BLK  [TP_THVT_100_RND_GND]  176.53 69.22 90 top
TP10  BLK  [TP_THVT_100_RND_GND]  161.04 100.97 180 top
TP11  BLK  [TP_THVT_100_RND_GND]  129.29 73.53 0 top
TP12  BLK  [TP_THVT_100_RND_GND]  129.41 85.85 0 top
TP13  GRN  [TP_THVT_100_RND]  3.17 109.73 0 top
TP14  BLU  [TP_THVT_100_RND]  83.95 98.43 0 top
TP15  BLU  [TP_THVT_100_RND]  133.91 89.66 0 top
TP16  BLU  [TP_THVT_100_RND]  133.91 85.85 0 top
TP17  BLU  [TP_THVT_100_RND]  38.23 60.83 0 top
TP18  BLU  [TP_THVT_100_RND]  160.15 96.52 90 top
TP19  BLU  [TP_THVT_100_RND]  172.72 69.22 90 top
TP20  BLU  [TP_THVT_100_RND]  176.53 65.41 90 top
TP21  GRN  [TP_THVT_100_RND]  165.48 86.36 180 top
TP22  BLK  [TP_THVT_100_RND_GND]  3.17 104.65 0 top
TP23  BLU  [TP_THVT_100_RND]  129.41 93.47 0 top
TP24  BLU  [TP_THVT_100_RND]  129.41 89.66 0 top
TP25  BLU  [TP_THVT_100_RND]  136.32 76.91 0 top
TP26  GRN  [TP_THVT_100_RND]  164.85 100.97 180 top
TP27  BLK  [TP_THVT_100_RND_GND]  24.52 39.5 0 top
TP28  GRN  [TP_THVT_100_RND]  158.11 66.04 90 top
TP29  RED  [TP_THVT_100_RND]  19.44 39.5 0 top
U1  5M80ZT100  [TQFP_100_551X551_20]  48.95 90.35 180 top
U2  DAC38J84  [BGA_144_10MMX10MM_0P80MM]  112.82 91.43 0 top
U3  FT2232H  [LQFP_64_402X402_20]  27.18 94.36 0 top
U4  93LC46B-I/MS  [MSOP_8_118X118_26]  9.52 107.19 180 top
U5  LMK04828  [QFN_64_360X360_0P50MM_PWRPAD]  86.11 59.06 270 top
U6  TPS7A4700  [QFN20_RGW_P65PITCH]  18.03 64.26 180 bottom
U7  TPS62420  [SON_DRC_10]  168.4 62.87 270 bottom
U8  TPS7A4700  [QFN20_RGW_P65PITCH]  156.59 77.72 270 bottom
U9  TPS74201  [QFN20_RGW_P65PITCH]  175.51 81.41 0 bottom
U10  TPS2400  [DBV5]  19.44 51.05 270 bottom
U11  TPS74201  [QFN20_RGW_P65PITCH]  175.39 96.01 0 bottom
U12  TLV70233DBV  [SOT_5_118X67_57]  21.34 110.74 270 top
U15  SN74AUP1T14  [SOP_5_85X55_26]  26.67 79.63 270 top
Y1  122.88MHz  [VCXO_6_CUSTOM]  107.57 40.71 180 top
Y2  12MHz w/ 10pF  [XTAL_4_SM_130X102]  14.07 101.76 135 top

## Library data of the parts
C1 C8 C12 C16 C54 C56 C96 C107 C145 C147 = CAP NP_1: tolerance: 10%
C3 C6 C10 C11 C15 C17 C18 C20-C22 = CAP0201: tolerance: 20%
C4 C5 C7 C9 C13 C14 C23-C28 C31-C40 C169-C171 C174-C197 = CAP0402: tolerance: 10%
C41 C47 C104 C105 C117 C119 C123 C129 C138 C149 = CAP_0603_0.01uF
C42 C55 = CAP NP: tolerance: 5%
C43 C49 = CAP_1206
C44 C46 C60 C61 C63 C82 C92 C98 C106 C109 C116 C127 C128 C134 C137 C150 C200 = CAP NP_0: tolerance: 10%
C45 C48 C97 C103 C108 C124 = CAP0603: tolerance: 10%
C50 C57-C59 C64-C75 C78 C79 C83 C86 C88 C89 C91 C93-C95 C121 C125 C152-C167 C207 C236 C340 C341 C343-C366 = CAPACITOR_NP_1: tolerance: 10%
C51 C52 C130 C139 C143 C144 C146 = CAP NP: tolerance: 10%
C53 C168 = CAP_0402_0.001uF_H
C62 C199 = CAP NP_0: tolerance: 5%
C80 C90 C122 C198 C206 = CAP_0402_0.1uF_H: tolerance: 10%
C81 C120 = CAP_0603_100pF_H
C84 = CAP_0402_2200pF_H
C85 = CAP_0402_10pF_H
C87 C133 C136 = CAP NP_2: tolerance: 10%
C99 C110 = CAP NP_0: tolerance: 20%
C100 C113 C151 = CAP_TANT_B_4.7uF_10V
C101 = CAP POL-B: tolerance: 10%
C102 = CAP0201: tolerance: 10%
C126 C135 = CAP_0603_2.2uF
C148 = CAP NP_1: tolerance: 2%
C172 C173 = CAP0402: tolerance: +/-10%
C235 = CAP POL: tolerance: 20%
D1 = LED_BLUE_1206
D2-D7 D11 = LED
D8 = LED_AMBER_1206
D9 = DIODE_MMSZ5235B
F1 = FUSE_0
FB2-FB10 FB17 FB34 = FERRITE_BEAD_0402_H
FB15 FB16 FB20 FB24 FB36 = FERRITE_BEAD
FB18 FB19 FB25 FB29 FB32 FB33 = FERRITE_BEAD_0402_120_H
FB30 FB31 = BEAD_NFM31P
GP1-GP8 = TEST POINT_0
J1 J3 J5 J7 J13 J18-J20 J22 = SMP_PLUG_SMT
J2 J4 J6 J8-J12 = SMA-END_JACK_142-0761-801_ROUND
J14 = USB_MINI_AB_MNE20-5G5P10
J15 = HEADER_2x5_100
J16 = CON_SMVT_40X10_ASP-134487-01
J17 = SMA-THVT_142-0701-201_REC
J21 = HEADER_2x4_100
J23 = CONN JACK PWR
J24 J25 = HEADER_2x10_100
JP1 JP3-JP6 = Jumper_1x3_100_0
JP2 = SMD_JUMPER_1x2
L17 L18 = IND1206
MT1-MT8 = MOUNTING_HOLE
PP1-PP7 PP9-PP11 = PROBE_POINT_22PAD
Q1 = PWR_MOSFET_CSD17313Q2
Q2-Q4 = MMBT2222A
R1 = Res_0805_Zero_H
R2 R4 R5 R7 R9 R11 R12 R14-R19 R21 R22 R24 R25 R27 R30 R33 R38 R40-R44 R46 R47 R49 R50 R71 R72 R90-R97 R101-R103 R113 R133 R183 R184 R187-R190 = R: tolerance: 5%
R3 R6 R8 R10 R13 R20 R23 R32 R37 R45 R48 R52 R112 R126-R128 R148 R150 R151 R153 R195-R202 = R: tolerance: 1%
R26 R28 R29 R31 R34-R36 R39 = Res_0402_49.9_H: tolerance: 1%
R51 = Res_0402_Zero
R53 R59 R81 R82 R85 R86 = RESISTOR
R54 R57 R58 R60-R64 R110 R111 = R_0: tolerance: 1%
R55 R56 R136 = Res_0402_10_H
R65 R66 R107 = R_1: tolerance: 1%
R67-R70 R75 R76 R79 R80 R83 R84 R89 R98 R122-R125 = Res_0402_249
R73 R74 R78 R87 = RESISTOR: tolerance: 1%
R77 R99 R100 R104 = Res_0402_49.9: tolerance: 1%
R88 R115 R116 R138 = Res_0402_100_H
R105 R106 R108 R109 R177 R191-R194 = Res_0402_Zero_H
R114 R117 R118 R129-R132 R134 = Res_0201_49.9
R119-R121 = Res_0603_Zero_H
R135 = Res_0402_1.8K
R143 = RES0603: tolerance: 1%
R173 = Res_0603_2.87K_H
R174 = Res_0603_3.65K
R175 = Res_0603_4.99K
R176 = Res_0603_634
R178 R185 R186 = Res_0402_Zero_DNI
R179-R182 = Res_0402_121
SJP1-SJP3 = JUMPER_SMD_L_0603
SW1 = SPST_PB_KT11P3JM_5
SW2 = SW_SMVT_SPST_4_BF3
T1 T3 T5 T7 = ADT4-1T_0
T2 T4 T6 T8 = TFMR_5_ETC1-1-13_4
TP1 TP2 = TESTPOINT_ORANGE
TP3-TP12 TP22 TP27 = TESTPOINT_BLK
TP13 TP21 TP26 TP28 = TESTPOINT_GRN
TP14-TP20 TP23-TP25 = TESTPOINT_BLUE
TP29 = TESTPOINT_RED
U1 = ALTERA_5M80ZT100
U2 = DAC38J84_144PIN
U3 = FT4232H_2
U4 = EEPROM
U5 = LMK04828_0
U6 U8 = TPS7A4700
U7 = TPS62420_SON10_1
U9 U11 = TPS74201/QFN20
U10 = TPS2400
U12 = TLV702XX-SOT23_0
U15 = SN74AUP1T14DCKR
Y1 = OSC_SM_6_TCO-2100-SERIES_2
Y2 = CRYSTAL1-4/SM

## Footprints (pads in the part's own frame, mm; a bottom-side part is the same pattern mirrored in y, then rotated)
0201
  rect 0.305x0.305 smd: 1(-0.305,0) 2(0.305,0)
0402
  rect 0.508x0.635 smd: 1(-0.508,0) 2(0.508,0)
0603
  rect 0.762x0.813 smd: 1(-0.787,0) 2(0.787,0)
0805
  rect 1.016x1.27 smd: 1(-1.016,0) 2(1.016,0)
1206
  rect 1.27x1.6 smd: 1(-1.524,0) 2(1.524,0)
1206_BEAD_NFM31P
  rect 1.016x1.575 smd: 1(-1.778,0) 3(1.778,0)
  rect 1.321x2.032 smd: 2(0,0)
1810
  rect 1.753x2.896 smd: 1(-2.629,0) 2(2.629,0)
BGA_144_10MMX10MM_0P80MM
  round 0.457 smd: A1(-4.4,-4.4) A2(-4.4,-3.6) A3(-4.4,-2.8) A4(-4.4,-2) A5(-4.4,-1.2) A6(-4.4,-0.4) A7(-4.4,0.4) A8(-4.4,1.2) A9(-4.4,2) A10(-4.4,2.8) A11(-4.4,3.6) A12(-4.4,4.4) B1(-3.6,-4.4) B2(-3.6,-3.6) B3(-3.6,-2.8) B4(-3.6,-2) B5(-3.6,-1.2) B6(-3.6,-0.4) B7(-3.6,0.4) B8(-3.6,1.2) B9(-3.6,2) B10(-3.6,2.8) B11(-3.6,3.6) B12(-3.6,4.4) C1(-2.8,-4.4) C2(-2.8,-3.6) C3(-2.8,-2.8) C4(-2.8,-2) C5(-2.8,-1.2) C6(-2.8,-0.4) C7(-2.8,0.4) C8(-2.8,1.2) C9(-2.8,2) C10(-2.8,2.8) C11(-2.8,3.6) C12(-2.8,4.4) D1(-2,-4.4) D2(-2,-3.6) D3(-2,-2.8) D4(-2,-2) D5(-2,-1.2) D6(-2,-0.4) D7(-2,0.4) D8(-2,1.2) D9(-2,2) D10(-2,2.8) D11(-2,3.6) D12(-2,4.4) E1(-1.2,-4.4) E2(-1.2,-3.6) E3(-1.2,-2.8) E4(-1.2,-2) E5(-1.2,-1.2) E6(-1.2,-0.4) E7(-1.2,0.4) E8(-1.2,1.2) E9(-1.2,2) E10(-1.2,2.8) E11(-1.2,3.6) E12(-1.2,4.4) F1(-0.4,-4.4) F2(-0.4,-3.6) F3(-0.4,-2.8) F4(-0.4,-2) F5(-0.4,-1.2) F6(-0.4,-0.4) F7(-0.4,0.4) F8(-0.4,1.2) F9(-0.4,2) F10(-0.4,2.8) F11(-0.4,3.6) F12(-0.4,4.4) G1(0.4,-4.4) G2(0.4,-3.6) G3(0.4,-2.8) G4(0.4,-2) G5(0.4,-1.2) G6(0.4,-0.4) G7(0.4,0.4) G8(0.4,1.2) G9(0.4,2) G10(0.4,2.8) G11(0.4,3.6) G12(0.4,4.4) H1(1.2,-4.4) H2(1.2,-3.6) H3(1.2,-2.8) H4(1.2,-2) H5(1.2,-1.2) H6(1.2,-0.4) H7(1.2,0.4) H8(1.2,1.2) H9(1.2,2) H10(1.2,2.8) H11(1.2,3.6) H12(1.2,4.4) J1(2,-4.4) J2(2,-3.6) J3(2,-2.8) J4(2,-2) J5(2,-1.2) J6(2,-0.4) J7(2,0.4) J8(2,1.2) J9(2,2) J10(2,2.8) J11(2,3.6) J12(2,4.4) K1(2.8,-4.4) K2(2.8,-3.6) K3(2.8,-2.8) K4(2.8,-2) K5(2.8,-1.2) K6(2.8,-0.4) K7(2.8,0.4) K8(2.8,1.2) K9(2.8,2) K10(2.8,2.8) K11(2.8,3.6) K12(2.8,4.4) L1(3.6,-4.4) L2(3.6,-3.6) L3(3.6,-2.8) L4(3.6,-2) L5(3.6,-1.2) L6(3.6,-0.4) L7(3.6,0.4) L8(3.6,1.2) L9(3.6,2) L10(3.6,2.8) L11(3.6,3.6) L12(3.6,4.4) M1(4.4,-4.4) M2(4.4,-3.6) M3(4.4,-2.8) M4(4.4,-2) M5(4.4,-1.2) M6(4.4,-0.4) M7(4.4,0.4) M8(4.4,1.2) M9(4.4,2) M10(4.4,2.8) M11(4.4,3.6) M12(4.4,4.4)
CON_RAPC722_JACK_THVT_3
  round 4.318 hole 3.556: 1(0,3.124)
  round 3.81 hole 3.048: 2(0,-3.124) 3(4.801,0.127)
CON_SMRT_USBMNE20_F
  round 0.025 hole 0.991 unplated: (0.65,2.2) (0.65,-2.2)
  rect 2.311x0.508 smd: 1(3.45,1.6) 2(3.45,0.8) 3(3.45,0) 4(3.45,-0.8) 5(3.45,-1.6)
  rect 2.489x2.007 smd: 6(-2.15,-4.45) 7(3.35,-4.45) 8(3.35,4.45) 9(-2.15,4.45)
CON_SMVT_40X10_ASP-134487-01
  round 1.27 hole 1.27 unplated: (-27.191,-3.048) (27.191,0)
  round 0.635 smd: A1(24.765,5.715) A2(23.495,5.715) A3(22.225,5.715) A4(20.955,5.715) A5(19.685,5.715) A6(18.415,5.715) A7(17.145,5.715) A8(15.875,5.715) A9(14.605,5.715) A10(13.335,5.715) A11(12.065,5.715) A12(10.795,5.715) A13(9.525,5.715) A14(8.255,5.715) A15(6.985,5.715) A16(5.715,5.715) A17(4.445,5.715) A18(3.175,5.715) A19(1.905,5.715) A20(0.635,5.715) A21(-0.635,5.715) A22(-1.905,5.715) A23(-3.175,5.715) A24(-4.445,5.715) A25(-5.715,5.715) A26(-6.985,5.715) A27(-8.255,5.715) A28(-9.525,5.715) A29(-10.795,5.715) A30(-12.065,5.715) A31(-13.335,5.715) A32(-14.605,5.715) A33(-15.875,5.715) A34(-17.145,5.715) A35(-18.415,5.715) A36(-19.685,5.715) A37(-20.955,5.715) A38(-22.225,5.715) A39(-23.495,5.715) A40(-24.765,5.715) B1(24.765,4.445) B2(23.495,4.445) B3(22.225,4.445) B4(20.955,4.445) B5(19.685,4.445) B6(18.415,4.445) B7(17.145,4.445) B8(15.875,4.445) B9(14.605,4.445) B10(13.335,4.445) B11(12.065,4.445) B12(10.795,4.445) B13(9.525,4.445) B14(8.255,4.445) B15(6.985,4.445) B16(5.715,4.445) B17(4.445,4.445) B18(3.175,4.445) B19(1.905,4.445) B20(0.635,4.445) B21(-0.635,4.445) B22(-1.905,4.445) B23(-3.175,4.445) B24(-4.445,4.445) B25(-5.715,4.445) B26(-6.985,4.445) B27(-8.255,4.445) B28(-9.525,4.445) B29(-10.795,4.445) B30(-12.065,4.445) B31(-13.335,4.445) B32(-14.605,4.445) B33(-15.875,4.445) B34(-17.145,4.445) B35(-18.415,4.445) B36(-19.685,4.445) B37(-20.955,4.445) B38(-22.225,4.445) B39(-23.495,4.445) B40(-24.765,4.445) C1(24.765,3.175) C2(23.495,3.175) C3(22.225,3.175) C4(20.955,3.175) C5(19.685,3.175) C6(18.415,3.175) C7(17.145,3.175) C8(15.875,3.175) C9(14.605,3.175) C10(13.335,3.175) C11(12.065,3.175) C12(10.795,3.175) C13(9.525,3.175) C14(8.255,3.175) C15(6.985,3.175) C16(5.715,3.175) C17(4.445,3.175) C18(3.175,3.175) C19(1.905,3.175) C20(0.635,3.175) C21(-0.635,3.175) C22(-1.905,3.175) C23(-3.175,3.175) C24(-4.445,3.175) C25(-5.715,3.175) C26(-6.985,3.175) C27(-8.255,3.175) C28(-9.525,3.175) C29(-10.795,3.175) C30(-12.065,3.175) C31(-13.335,3.175) C32(-14.605,3.175) C33(-15.875,3.175) C34(-17.145,3.175) C35(-18.415,3.175) C36(-19.685,3.175) C37(-20.955,3.175) C38(-22.225,3.175) C39(-23.495,3.175) C40(-24.765,3.175) D1(24.765,1.905) D2(23.495,1.905) D3(22.225,1.905) D4(20.955,1.905) D5(19.685,1.905) D6(18.415,1.905) D7(17.145,1.905) D8(15.875,1.905) D9(14.605,1.905) D10(13.335,1.905) D11(12.065,1.905) D12(10.795,1.905) D13(9.525,1.905) D14(8.255,1.905) D15(6.985,1.905) D16(5.715,1.905) D17(4.445,1.905) D18(3.175,1.905) D19(1.905,1.905) D20(0.635,1.905) D21(-0.635,1.905) D22(-1.905,1.905) D23(-3.175,1.905) D24(-4.445,1.905) D25(-5.715,1.905) D26(-6.985,1.905) D27(-8.255,1.905) D28(-9.525,1.905) D29(-10.795,1.905) D30(-12.065,1.905) D31(-13.335,1.905) D32(-14.605,1.905) D33(-15.875,1.905) D34(-17.145,1.905) D35(-18.415,1.905) D36(-19.685,1.905) D37(-20.955,1.905) D38(-22.225,1.905) D39(-23.495,1.905) D40(-24.765,1.905) E1(24.765,0.635) E2(23.495,0.635) E3(22.225,0.635) E4(20.955,0.635) E5(19.685,0.635) E6(18.415,0.635) E7(17.145,0.635) E8(15.875,0.635) E9(14.605,0.635) E10(13.335,0.635) E11(12.065,0.635) E12(10.795,0.635) E13(9.525,0.635) E14(8.255,0.635) E15(6.985,0.635) E16(5.715,0.635) E17(4.445,0.635) E18(3.175,0.635) E19(1.905,0.635) E20(0.635,0.635) E21(-0.635,0.635) E22(-1.905,0.635) E23(-3.175,0.635) E24(-4.445,0.635) E25(-5.715,0.635) E26(-6.985,0.635) E27(-8.255,0.635) E28(-9.525,0.635) E29(-10.795,0.635) E30(-12.065,0.635) E31(-13.335,0.635) E32(-14.605,0.635) E33(-15.875,0.635) E34(-17.145,0.635) E35(-18.415,0.635) E36(-19.685,0.635) E37(-20.955,0.635) E38(-22.225,0.635) E39(-23.495,0.635) E40(-24.765,0.635) F1(24.765,-0.635) F2(23.495,-0.635) F3(22.225,-0.635) F4(20.955,-0.635) F5(19.685,-0.635) F6(18.415,-0.635) F7(17.145,-0.635) F8(15.875,-0.635) F9(14.605,-0.635) F10(13.335,-0.635) F11(12.065,-0.635) F12(10.795,-0.635) F13(9.525,-0.635) F14(8.255,-0.635) F15(6.985,-0.635) F16(5.715,-0.635) F17(4.445,-0.635) F18(3.175,-0.635) F19(1.905,-0.635) F20(0.635,-0.635) F21(-0.635,-0.635) F22(-1.905,-0.635) F23(-3.175,-0.635) F24(-4.445,-0.635) F25(-5.715,-0.635) F26(-6.985,-0.635) F27(-8.255,-0.635) F28(-9.525,-0.635) F29(-10.795,-0.635) F30(-12.065,-0.635) F31(-13.335,-0.635) F32(-14.605,-0.635) F33(-15.875,-0.635) F34(-17.145,-0.635) F35(-18.415,-0.635) F36(-19.685,-0.635) F37(-20.955,-0.635) F38(-22.225,-0.635) F39(-23.495,-0.635) F40(-24.765,-0.635) G1(24.765,-1.905) G2(23.495,-1.905) G3(22.225,-1.905) G4(20.955,-1.905) G5(19.685,-1.905) G6(18.415,-1.905) G7(17.145,-1.905) G8(15.875,-1.905) G9(14.605,-1.905) G10(13.335,-1.905) G11(12.065,-1.905) G12(10.795,-1.905) G13(9.525,-1.905) G14(8.255,-1.905) G15(6.985,-1.905) G16(5.715,-1.905) G17(4.445,-1.905) G18(3.175,-1.905) G19(1.905,-1.905) G20(0.635,-1.905) G21(-0.635,-1.905) G22(-1.905,-1.905) G23(-3.175,-1.905) G24(-4.445,-1.905) G25(-5.715,-1.905) G26(-6.985,-1.905) G27(-8.255,-1.905) G28(-9.525,-1.905) G29(-10.795,-1.905) G30(-12.065,-1.905) G31(-13.335,-1.905) G32(-14.605,-1.905) G33(-15.875,-1.905) G34(-17.145,-1.905) G35(-18.415,-1.905) G36(-19.685,-1.905) G37(-20.955,-1.905) G38(-22.225,-1.905) G39(-23.495,-1.905) G40(-24.765,-1.905) H1(24.765,-3.175) H2(23.495,-3.175) H3(22.225,-3.175) H4(20.955,-3.175) H5(19.685,-3.175) H6(18.415,-3.175) H7(17.145,-3.175) H8(15.875,-3.175) H9(14.605,-3.175) H10(13.335,-3.175) H11(12.065,-3.175) H12(10.795,-3.175) H13(9.525,-3.175) H14(8.255,-3.175) H15(6.985,-3.175) H16(5.715,-3.175) H17(4.445,-3.175) H18(3.175,-3.175) H19(1.905,-3.175) H20(0.635,-3.175) H21(-0.635,-3.175) H22(-1.905,-3.175) H23(-3.175,-3.175) H24(-4.445,-3.175) H25(-5.715,-3.175) H26(-6.985,-3.175) H27(-8.255,-3.175) H28(-9.525,-3.175) H29(-10.795,-3.175) H30(-12.065,-3.175) H31(-13.335,-3.175) H32(-14.605,-3.175) H33(-15.875,-3.175) H34(-17.145,-3.175) H35(-18.415,-3.175) H36(-19.685,-3.175) H37(-20.955,-3.175) H38(-22.225,-3.175) H39(-23.495,-3.175) H40(-24.765,-3.175) J1(24.765,-4.445) J2(23.495,-4.445) J3(22.225,-4.445) J4(20.955,-4.445) J5(19.685,-4.445) J6(18.415,-4.445) J7(17.145,-4.445) J8(15.875,-4.445) J9(14.605,-4.445) J10(13.335,-4.445) J11(12.065,-4.445) J12(10.795,-4.445) J13(9.525,-4.445) J14(8.255,-4.445) J15(6.985,-4.445) J16(5.715,-4.445) J17(4.445,-4.445) J18(3.175,-4.445) J19(1.905,-4.445) J20(0.635,-4.445) J21(-0.635,-4.445) J22(-1.905,-4.445) J23(-3.175,-4.445) J24(-4.445,-4.445) J25(-5.715,-4.445) J26(-6.985,-4.445) J27(-8.255,-4.445) J28(-9.525,-4.445) J29(-10.795,-4.445) J30(-12.065,-4.445) J31(-13.335,-4.445) J32(-14.605,-4.445) J33(-15.875,-4.445) J34(-17.145,-4.445) J35(-18.415,-4.445) J36(-19.685,-4.445) J37(-20.955,-4.445) J38(-22.225,-4.445) J39(-23.495,-4.445) J40(-24.765,-4.445) K1(24.765,-5.715) K2(23.495,-5.715) K3(22.225,-5.715) K4(20.955,-5.715) K5(19.685,-5.715) K6(18.415,-5.715) K7(17.145,-5.715) K8(15.875,-5.715) K9(14.605,-5.715) K10(13.335,-5.715) K11(12.065,-5.715) K12(10.795,-5.715) K13(9.525,-5.715) K14(8.255,-5.715) K15(6.985,-5.715) K16(5.715,-5.715) K17(4.445,-5.715) K18(3.175,-5.715) K19(1.905,-5.715) K20(0.635,-5.715) K21(-0.635,-5.715) K22(-1.905,-5.715) K23(-3.175,-5.715) K24(-4.445,-5.715) K25(-5.715,-5.715) K26(-6.985,-5.715) K27(-8.255,-5.715) K28(-9.525,-5.715) K29(-10.795,-5.715) K30(-12.065,-5.715) K31(-13.335,-5.715) K32(-14.605,-5.715) K33(-15.875,-5.715) K34(-17.145,-5.715) K35(-18.415,-5.715) K36(-19.685,-5.715) K37(-20.955,-5.715) K38(-22.225,-5.715) K39(-23.495,-5.715) K40(-24.765,-5.715)
DBV5
  rect 1.27x0.508 smd: 1(-1.1,0.95) 2(-1.1,0) 3(-1.1,-0.95) 4(1.1,-0.95) 5(1.1,0.95)
DIODE_SM_SOD_123
  rect 0.914x1.219 smd: 1(-1.638,0) 2(1.638,0)
HDR_THVT_1X2_100_M
  rect 1.473x1.473 hole 0.965: 1(0,0)
  round 1.473 hole 0.965: 2(0,-2.54)
HDR_THVT_1X3_100_M
  rect 1.575x1.575 hole 1.016: 1(0,0)
  round 1.575 hole 1.016: 2(0,-2.54) 3(0,-5.08)
HDR_THVT_2X4_100_M
  rect 1.473x1.473 hole 0.965: 1(0,0)
  round 1.473 hole 0.965: 2(2.54,0) 3(0,-2.54) 4(2.54,-2.54) 5(0,-5.08) 6(2.54,-5.08) 7(0,-7.62) 8(2.54,-7.62)
HDR_THVT_2X5_100_M
  rect 1.473x1.473 hole 0.965: 1(0,0)
  round 1.473 hole 0.965: 2(2.54,0) 3(0,-2.54) 4(2.54,-2.54) 5(0,-5.08) 6(2.54,-5.08) 7(0,-7.62) 8(2.54,-7.62) 9(0,-10.16) 10(2.54,-10.16)
HDR_THVT_2X10_100_M
  rect 1.473x1.473 hole 0.965: 1(0,0)
  round 1.473 hole 0.965: 2(2.54,0) 3(0,-2.54) 4(2.54,-2.54) 5(0,-5.08) 6(2.54,-5.08) 7(0,-7.62) 8(2.54,-7.62) 9(0,-10.16) 10(2.54,-10.16) 11(0,-12.7) 12(2.54,-12.7) 13(0,-15.24) 14(2.54,-15.24) 15(0,-17.78) 16(2.54,-17.78) 17(0,-20.32) 18(2.54,-20.32) 19(0,-22.86) 20(2.54,-22.86)
IND_0402
  rect 0.406x0.66 smd: 1(-0.432,0) 2(0.432,0)
JUMPER_SMD_L_0603
  rect 0.762x0.813 smd: 1(-1.067,0) 2(0.508,0) 3(0.508,1.575)
LED_1206
  rect 1.27x1.6 smd: 1(-1.524,0) 2(1.524,0)
LPS3015
  custom 0.286x0.286 smd: 1(-1.143,0) 2(1.143,0)
LQFP_64_402X402_20
  round 1.016 smd: (-6.35,6.35) (6.35,-6.35)
  rect 2.032x0.33 smd: 1(-5.625,3.75) 2(-5.625,3.25) 3(-5.625,2.75) 4(-5.625,2.25) 5(-5.625,1.75) 6(-5.625,1.25) 7(-5.625,0.75) 8(-5.625,0.25) 9(-5.625,-0.25) 10(-5.625,-0.75) 11(-5.625,-1.25) 12(-5.625,-1.75) 13(-5.625,-2.25) 14(-5.625,-2.75) 15(-5.625,-3.25) 16(-5.625,-3.75) 33(5.625,-3.75) 34(5.625,-3.25) 35(5.625,-2.75) 36(5.625,-2.25) 37(5.625,-1.75) 38(5.625,-1.25) 39(5.625,-0.75) 40(5.625,-0.25) 41(5.625,0.25) 42(5.625,0.75) 43(5.625,1.25) 44(5.625,1.75) 45(5.625,2.25) 46(5.625,2.75) 47(5.625,3.25) 48(5.625,3.75)
  rect 0.33x2.032 smd: 17(-3.75,-5.625) 18(-3.25,-5.625) 19(-2.75,-5.625) 20(-2.25,-5.625) 21(-1.75,-5.625) 22(-1.25,-5.625) 23(-0.75,-5.625) 24(-0.25,-5.625) 25(0.25,-5.625) 26(0.75,-5.625) 27(1.25,-5.625) 28(1.75,-5.625) 29(2.25,-5.625) 30(2.75,-5.625) 31(3.25,-5.625) 32(3.75,-5.625) 49(3.75,5.625) 50(3.25,5.625) 51(2.75,5.625) 52(2.25,5.625) 53(1.75,5.625) 54(1.25,5.625) 55(0.75,5.625) 56(0.25,5.625) 57(-0.25,5.625) 58(-0.75,5.625) 59(-1.25,5.625) 60(-1.75,5.625) 61(-2.25,5.625) 62(-2.75,5.625) 63(-3.25,5.625) 64(-3.75,5.625)
MFG125_PLATED
  round 2.286 hole 3.175 unplated: (0,0)
MOSFET_8_2MMX2MM_0P65
  rect 0.4x0.47 smd: 1(-0.653,-0.91) 2(-0.003,-0.91) 3(0.647,-0.91) 4(0.647,0.91) 5(-0.003,0.91) 6(-0.653,0.91)
  rect 0.406x0.762 smd: 7(0.647,0.109)
  rect 1.016x1.016 smd: 8(-0.308,0)
MSOP_8_118X118_26
  rect 1.575x0.406 smd: 1(-2.225,0.975) 2(-2.225,0.325) 3(-2.225,-0.325) 4(-2.225,-0.975) 5(2.225,-0.975) 6(2.225,-0.325) 7(2.225,0.325) 8(2.225,0.975)
PROBE_POINT_22PAD
  round 0.508 smd: 1(0,0)
QFN20_RGW_P65PITCH
  custom 0.09x0.09 smd: 1(-2.607,1.3) 2(-2.607,0.65) 3(-2.607,0) 4(-2.607,-0.65) 5(-2.607,-1.3) 6(-1.3,-2.607) 7(-0.65,-2.607) 8(0,-2.607) 9(0.65,-2.607) 10(1.3,-2.607) 11(2.607,-1.3) 12(2.607,-0.65) 13(2.607,0) 14(2.607,0.65) 15(2.607,1.3) 16(1.3,2.607) 17(0.65,2.607) 18(0,2.607) 19(-0.65,2.607) 20(-1.3,2.607)
  rect 3.302x3.302 smd: 21(0,0)
QFN_64_360X360_0P50MM_PWRPAD
  oval 1.016x0.305 smd: 1(-4.58,3.753) 2(-4.58,3.252) 3(-4.58,2.752) 4(-4.58,2.252) 5(-4.58,1.751) 6(-4.58,1.251) 7(-4.58,0.751) 8(-4.58,0.25) 9(-4.58,-0.25) 10(-4.58,-0.751) 11(-4.58,-1.251) 12(-4.58,-1.751) 13(-4.58,-2.252) 14(-4.58,-2.752) 15(-4.58,-3.252) 16(-4.58,-3.753) 33(4.58,-3.753) 34(4.58,-3.252) 35(4.58,-2.752) 36(4.58,-2.252) 37(4.58,-1.751) 38(4.58,-1.251) 39(4.58,-0.751) 40(4.58,-0.25) 41(4.58,0.25) 42(4.58,0.751) 43(4.58,1.251) 44(4.58,1.751) 45(4.58,2.252) 46(4.58,2.752) 47(4.58,3.252) 48(4.58,3.753)
  oval 0.305x1.016 smd: 17(-3.753,-4.58) 18(-3.252,-4.58) 19(-2.752,-4.58) 20(-2.252,-4.58) 21(-1.751,-4.58) 22(-1.251,-4.58) 23(-0.751,-4.58) 24(-0.25,-4.58) 25(0.25,-4.58) 26(0.751,-4.58) 27(1.251,-4.58) 28(1.751,-4.58) 29(2.252,-4.58) 30(2.752,-4.58) 31(3.252,-4.58) 32(3.753,-4.58) 49(3.753,4.58) 50(3.252,4.58) 51(2.752,4.58) 52(2.252,4.58) 53(1.751,4.58) 54(1.251,4.58) 55(0.751,4.58) 56(0.25,4.58) 57(-0.25,4.58) 58(-0.751,4.58) 59(-1.251,4.58) 60(-1.751,4.58) 61(-2.252,4.58) 62(-2.752,4.58) 63(-3.252,4.58) 64(-3.753,4.58)
  rect 7.366x7.366 smd: 65(0,0)
SMA_SMEL_DUAL_PSF-S01_250X215
  rect 0.508x4.064 smd: 1(0,-2.032)
  rect 3.048x4.064 smd: 2(-3.556,-2.032) 3(3.556,-2.032) 4(-3.556,-2.032) 5(3.556,-2.032)
SMA_THVT_312X312
  round 2.337 hole 1.575: 1(0,0)
  round 2.464 hole 1.702: 2(-2.54,2.54) 3(2.54,2.54) 4(2.54,-2.54) 5(-2.54,-2.54)
SMP_B120
  rect 0.508x1.321 smd: 1(0,-3.1)
  custom 1.3x1.3 smd: 2(0,0)
SON_DRC_10
  rect 0.864x0.305 smd: 1(-1.5,1) 2(-1.5,0.5) 3(-1.5,0) 4(-1.5,-0.5) 5(-1.5,-1) 6(1.5,-1) 7(1.5,-0.5) 8(1.5,0) 9(1.5,0.5) 10(1.5,1)
  rect 1.524x3 smd: 11(0,0)
SOP_5_85X55_26
  rect 0.457x1.143 smd: 1(-0.65,-0.82) 2(0,-0.82) 3(0.65,-0.82) 4(0.65,0.82) 5(-0.65,0.82)
SOT_5_118X67_57
  rect 0.61x1.524 smd: 1(-0.95,-1.75) 2(0,-1.75) 3(0.95,-1.75) 4(0.95,1.75) 5(-0.95,1.75)
SOT_416_3_63X31
  rect 0.508x0.356 smd: 1(0,-0.152) 2(0,-1.168) 3(1.295,-0.66)
SW_SMVT_RESET
  rect 1.575x3.175 smd: 1(-1.968,2.591) 2(-1.968,-2.591) 3(1.968,2.591) 4(1.968,-2.591)
SW_THVT_SPST_4_B3F
  rect 1.473x1.473 hole 0.965: 1(-3.25,2.25)
  round 1.473 hole 0.965: 2(3.25,2.25) 3(-3.25,-2.25) 4(3.25,-2.25)
TANT_B
  rect 2.032x2.286 smd: 1(-1.524,0) 2(1.524,0)
TESTPAD20_30
  rect 0.813x0.508 smd: 1(0,0)
TFMR_6_RF_DUAL_FOOTPRINT
  rect 1.27x1.778 smd: 1(-2.54,-2.794) 2(0,-2.794) 3(2.54,-2.794) 4(2.54,2.794) 5(0,2.794) 6(-2.54,2.794)
TP_THVT_100_RND
  round 2.54 hole 1.016: 1(0,0)
TP_THVT_100_RND_GND
  round 2.54 hole 1.016: 1(0,0)
TQFP_100_551X551_20
  rect 1.778x0.33 smd: 1(-7.7,6) 2(-7.7,5.5) 3(-7.7,5) 4(-7.7,4.5) 5(-7.7,4) 6(-7.7,3.5) 7(-7.7,3) 8(-7.7,2.5) 9(-7.7,2) 10(-7.7,1.5) 11(-7.7,1) 12(-7.7,0.5) 13(-7.7,0) 14(-7.7,-0.5) 15(-7.7,-1) 16(-7.7,-1.5) 17(-7.7,-2) 18(-7.7,-2.5) 19(-7.7,-3) 20(-7.7,-3.5) 21(-7.7,-4) 22(-7.7,-4.5) 23(-7.7,-5) 24(-7.7,-5.5) 25(-7.7,-6) 51(7.7,-6) 52(7.7,-5.5) 53(7.7,-5) 54(7.7,-4.5) 55(7.7,-4) 56(7.7,-3.5) 57(7.7,-3) 58(7.7,-2.5) 59(7.7,-2) 60(7.7,-1.5) 61(7.7,-1) 62(7.7,-0.5) 63(7.7,0) 64(7.7,0.5) 65(7.7,1) 66(7.7,1.5) 67(7.7,2) 68(7.7,2.5) 69(7.7,3) 70(7.7,3.5) 71(7.7,4) 72(7.7,4.5) 73(7.7,5) 74(7.7,5.5) 75(7.7,6)
  rect 0.33x1.778 smd: 26(-6,-7.7) 27(-5.5,-7.7) 28(-5,-7.7) 29(-4.5,-7.7) 30(-4,-7.7) 31(-3.5,-7.7) 32(-3,-7.7) 33(-2.5,-7.7) 34(-2,-7.7) 35(-1.5,-7.7) 36(-1,-7.7) 37(-0.5,-7.7) 38(0,-7.7) 39(0.5,-7.7) 40(1,-7.7) 41(1.5,-7.7) 42(2,-7.7) 43(2.5,-7.7) 44(3,-7.7) 45(3.5,-7.7) 46(4,-7.7) 47(4.5,-7.7) 48(5,-7.7) 49(5.5,-7.7) 50(6,-7.7) 76(6,7.7) 77(5.5,7.7) 78(5,7.7) 79(4.5,7.7) 80(4,7.7) 81(3.5,7.7) 82(3,7.7) 83(2.5,7.7) 84(2,7.7) 85(1.5,7.7) 86(1,7.7) 87(0.5,7.7) 88(0,7.7) 89(-0.5,7.7) 90(-1,7.7) 91(-1.5,7.7) 92(-2,7.7) 93(-2.5,7.7) 94(-3,7.7) 95(-3.5,7.7) 96(-4,7.7) 97(-4.5,7.7) 98(-5,7.7) 99(-5.5,7.7) 100(-6,7.7)
